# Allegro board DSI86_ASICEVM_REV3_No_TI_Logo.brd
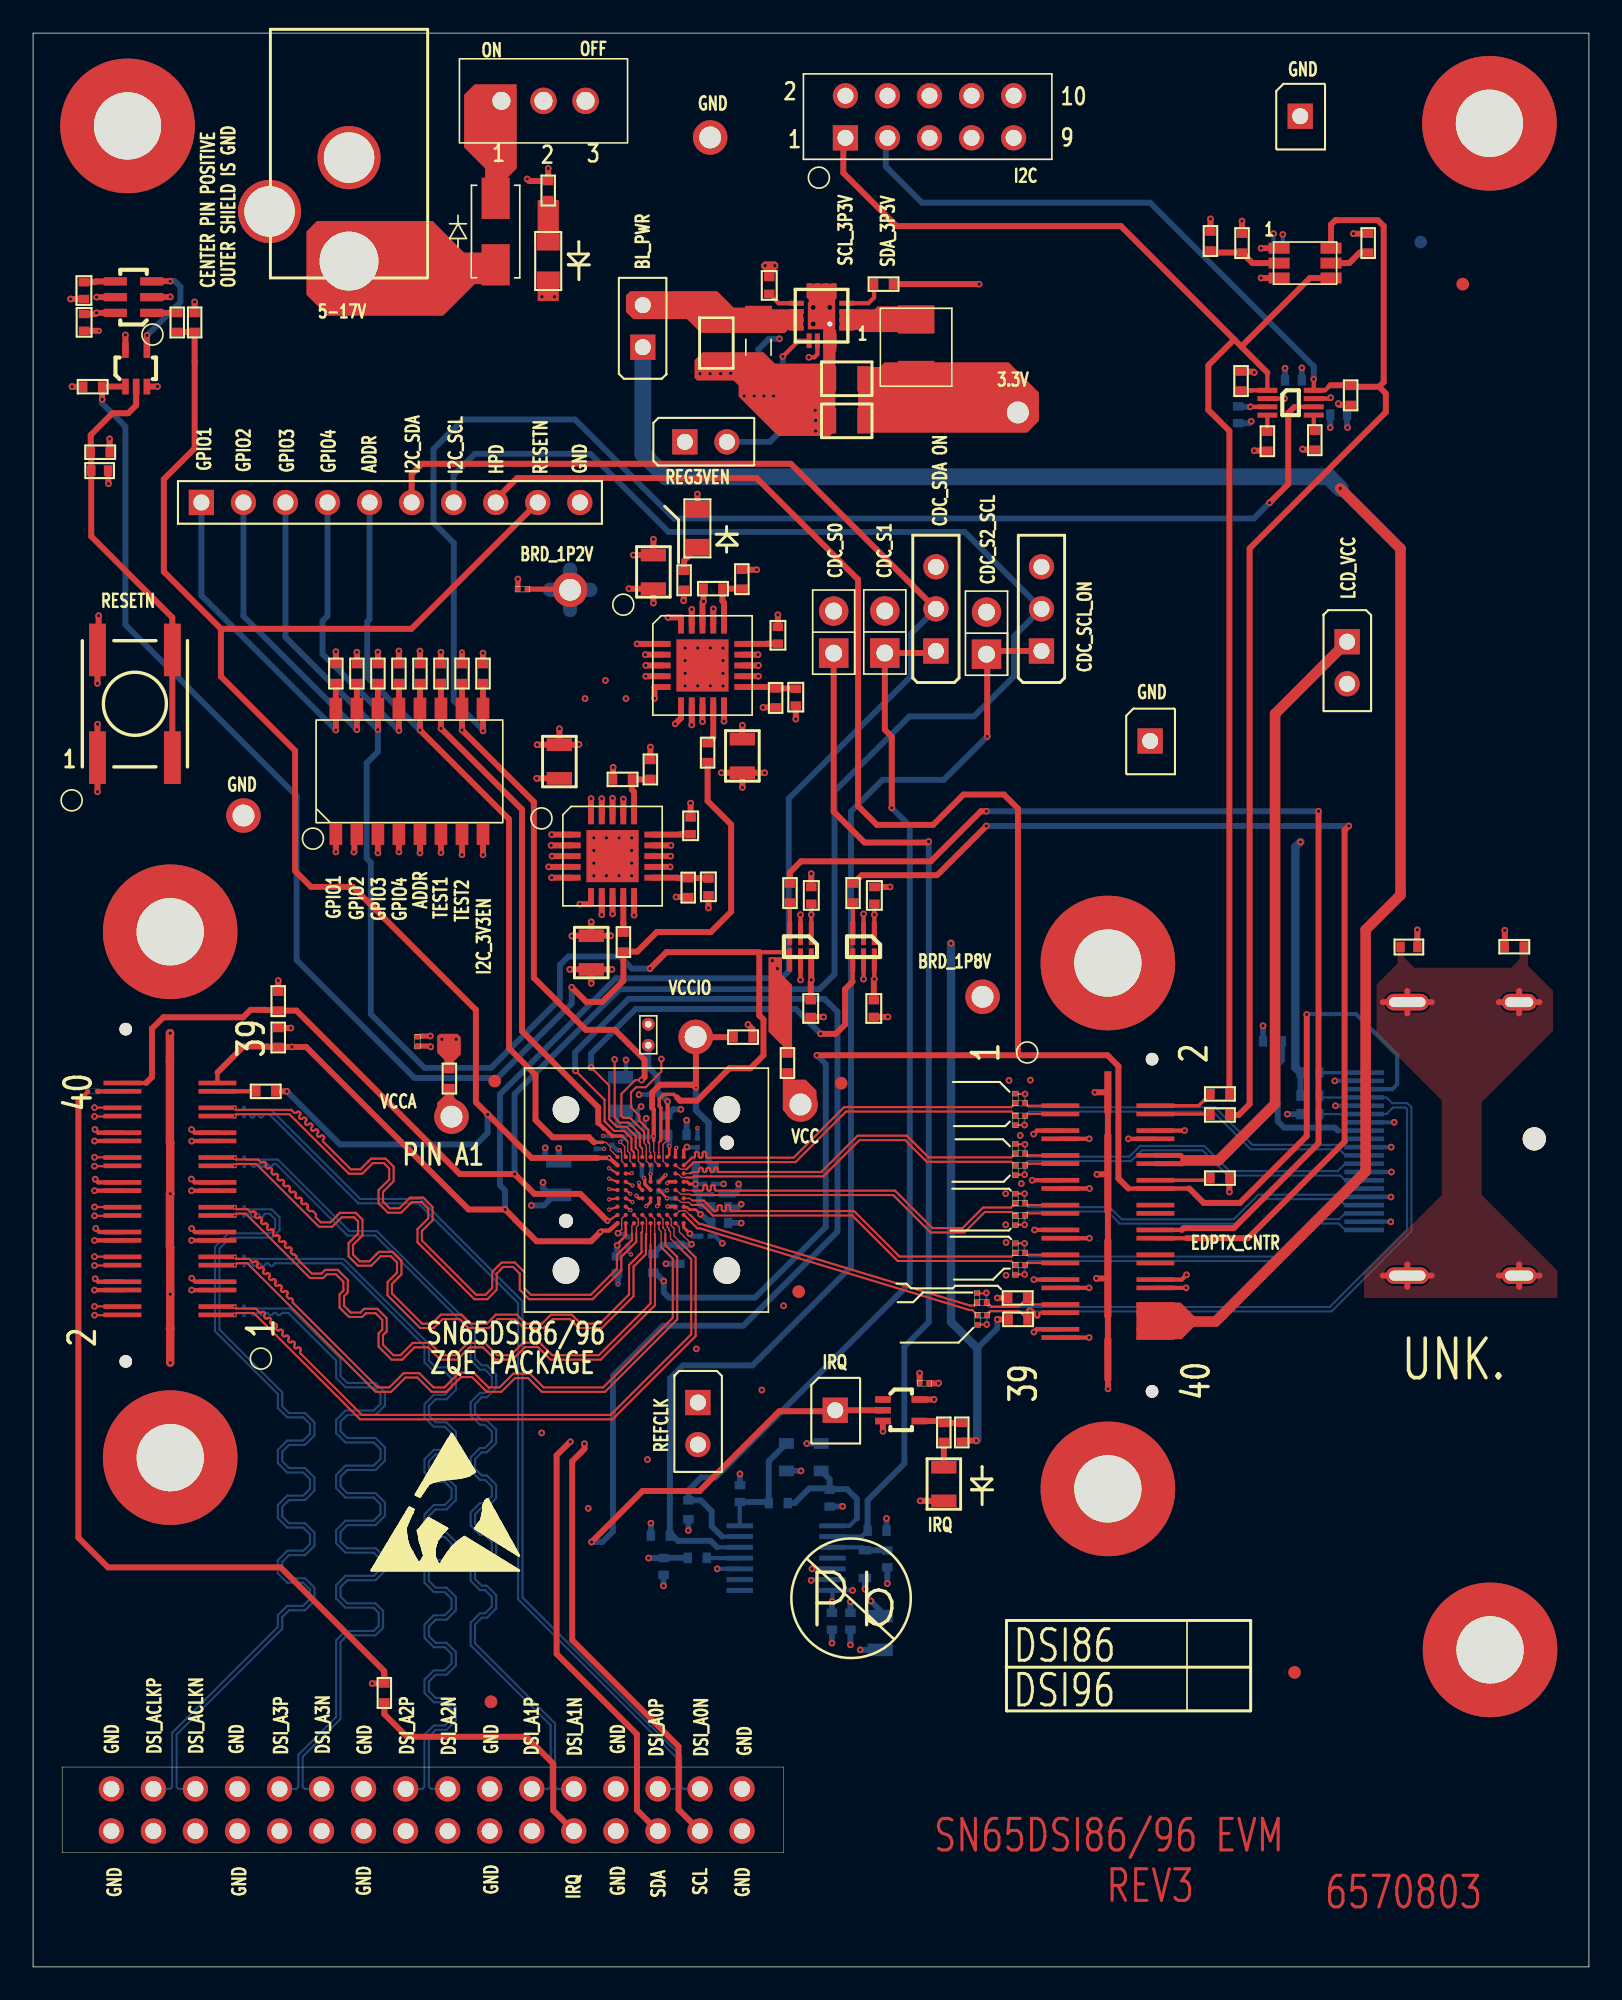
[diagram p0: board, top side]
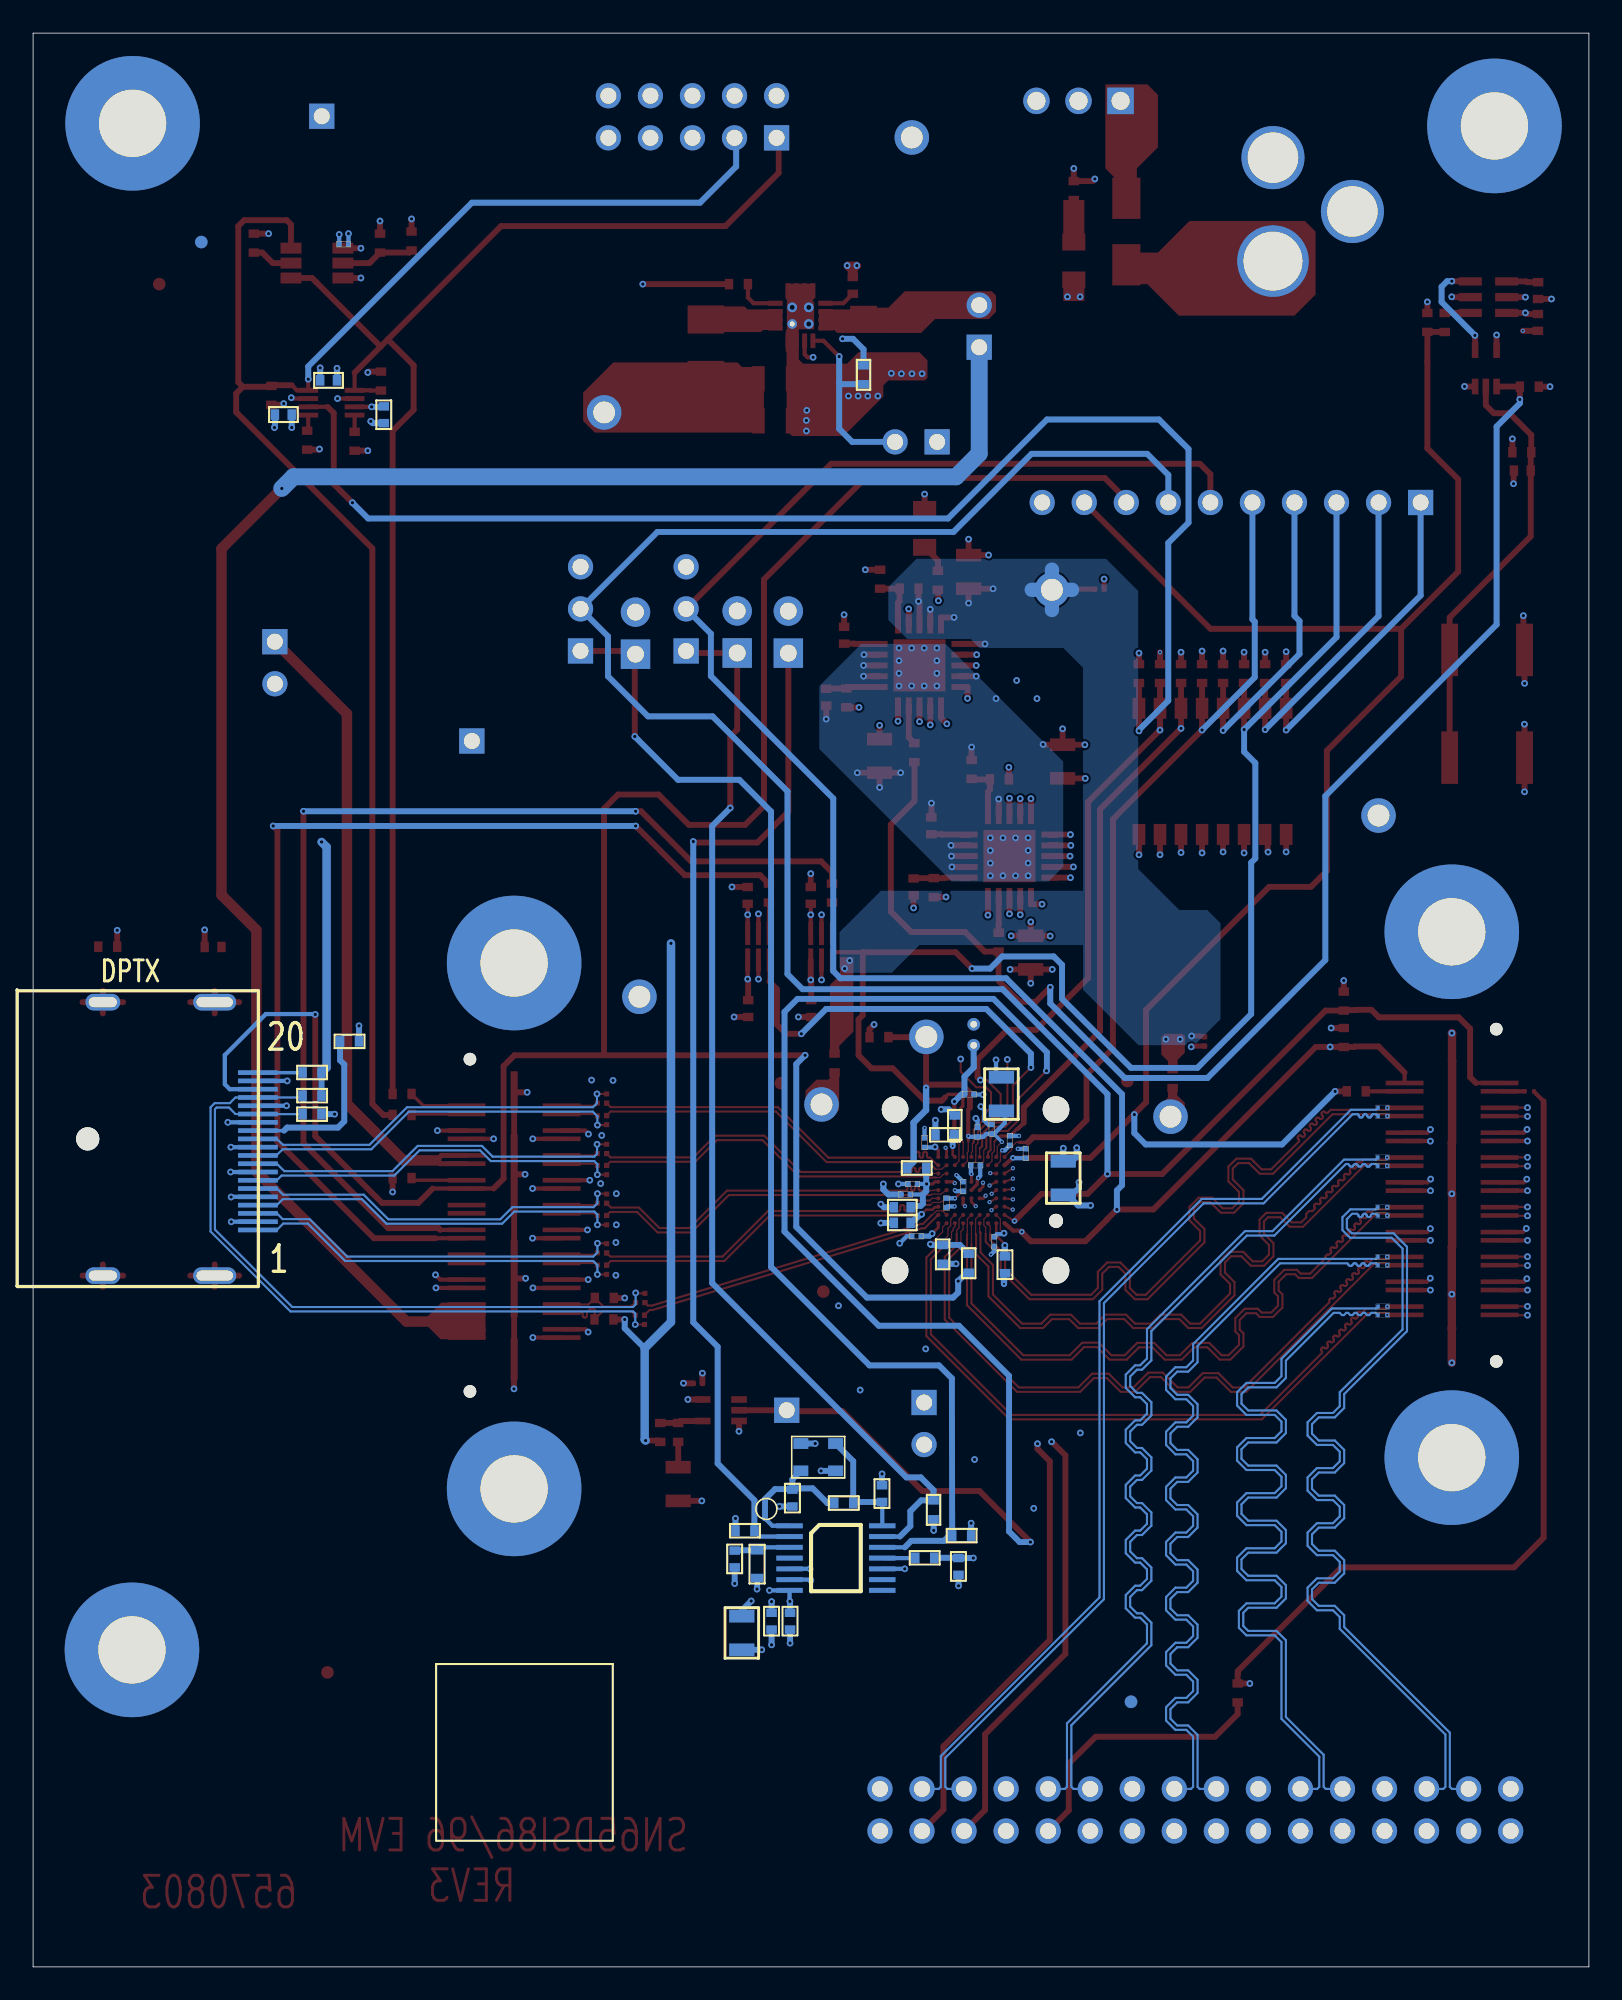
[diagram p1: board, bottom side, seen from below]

Outline 93.98 x 116.75 mm; copper layers: TOP, L2_GND, L3_SIG, L4_PWR, L5_GND, BOTTOM. Coordinates in mm from the lower left corner of the outline.
Outline path: 0,116.75 0,0 93.98,0 93.98,116.75 0,116.75

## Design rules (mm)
constraint set DEFAULT: min track width 0.356
net group AUX: nets AUXN AUXP
net group DIFFPAIR5: nets DSI_A0N DSI_A0P
net group DIFFPAIR6: nets DSI_A1N DSI_A1P
net group DIFFPAIR7: nets DSI_A2N DSI_A2P
net group DIFFPAIR8: nets DSI_A3N DSI_A3P
net group DIFFPAIR9: nets DSI_ACLKN DSI_ACLKP
net group DIFFPAIR10: nets DSI_B0N DSI_B0P
net group DIFFPAIR11: nets DSI_B1N DSI_B1P
net group DIFFPAIR12: nets DSI_B2N DSI_B2P
net group DIFFPAIR13: nets DSI_B3N DSI_B3P
net group DIFFPAIR14: nets DSI_BCLKN DSI_BCLKP
net group DIFFPAIR35: nets FX_CLKN FX_CLKP
net group DIFFPAIR36: nets FX_N0 FX_P0
net group DIFFPAIR37: nets FX_N1 FX_P1
net group DIFFPAIR38: nets FX_N2 FX_P2
net group DIFFPAIR39: nets FX_N3 FX_P3
net group DP_AUX: nets DP_AUXN DP_AUXP
net group EDP_AUX: nets EDP_AUXN EDP_AUXP
net group EDP_ML0: nets EDP_ML0N EDP_ML0P
net group EDP_ML1: nets EDP_ML1N EDP_ML1P
net group EDP_ML2: nets EDP_ML2N EDP_ML2P
net group EDP_ML3: nets EDP_ML3N EDP_ML3P
net group DP_M: nets DP_ML0N DP_ML0P DP_ML1N DP_ML1P DP_ML2N DP_ML2P DP_ML3N DP_ML3P
net group H_DDSS: nets I2C_SCL
net group ML: nets ML0N ML0P ML1N ML1P ML2N ML2P ML3N ML3P

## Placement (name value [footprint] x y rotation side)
C1  10uF  [CC0805]  35.49 51.68 90 bottom
C2  1.0uF  [CC0402]  35.26 42.95 270 bottom
C3  0.1uF  [CC0201]  37.33 48.4 180 bottom
C4  0.1uF  [CC0201]  36.07 50.29 90 bottom
C5  0.01uF  [CC0201]  37.8 47.4 270 bottom
C6  0.1uF  [CC0201]  36.93 50.11 90 bottom
C7  0.1uF  [CC0201]  40.34 44.12 0 bottom
C8  0.01uF  [CC0201]  40.56 47.27 0 bottom
C9  0.1uF  [CC0201]  53.55 35.23 0 top
C10  DNI  [CC0201]  34.01 48.83 90 bottom
C11  1.0uF  [CC0402]  40.92 44.91 0 bottom
C22  220pF  [CC0402]  3.09 101.77 270 top
C23  0.1uF  [CC0402]  3.1 99.85 270 top
C24  18pF  [CC0402]  3.46 90.36 0 top
C25  DNI  [CC0402]  48.13 27.75 90 bottom
C26  DNI  [CC0402]  42.69 29.13 270 bottom
C27  22uF  [CC0805]  51.17 21.18 270 bottom
C28  1.0uF  [CC0402]  78.31 93.71 0 bottom
C29  0.1uF  [CC0402]  76.69 95.81 180 bottom
C30  0.1uF  [CC0402]  72.78 94.27 270 bottom
C31  0.1uF  [CC0402]  51.58 25.19 270 bottom
C32  0.1uF  [CC0402]  49.36 21.43 270 bottom
C33  0.1uF  [CC0402]  48.24 21.43 270 bottom
C35  10uF  [CC0805]  41.27 99.06 270 top
C36  22uF  [CC1206]  43.81 97.79 270 top
C37  22uF  [CC0805]  50.16 93.34 180 top
C38  10uF  [CC0805]  50.16 95.89 180 top
C39  10uF  [CC0805]  42.84 74.13 270 top
C40  3.3nF  [CC0402]  44.45 100.97 90 top
C42  10uF  [CC0805]  37.47 83.21 90 top
C43  0.01uF  [CC0402]  46.09 77.22 270 top
C44  DNI  [CC0402]  44.98 79.84 90 top
C45  10uF  [CC0805]  33.72 62.26 270 top
C46  10uF  [CC0805]  31.79 71.76 90 top
C47  0.01uF  [CC0402]  40.81 65.77 270 top
C48  DNI  [CC0402]  39.7 68.34 90 top
C55  DNI  [CC0402]  38.07 24.74 270 bottom
C56  0.1uF  [CC0201]  38.81 46.41 270 bottom
C57  10uF  [CC0805]  31.75 48.64 270 bottom
C58  0.01uF  [CC0201]  34.97 49.61 90 bottom
C59  0.1uF  [CC0201]  35.93 44.07 270 bottom
C60  0.01uF  [CC0201]  40.13 49.48 90 bottom
C61  0.1uF  [CC0201]  23.21 56.15 270 top
C62  0.1uF  [CC0201]  29.84 83.19 180 top
C63  DNI  [CC0201]  59.33 52.15 0 top
C64  DNI  [CC0201]  59.33 51.38 0 top
C65  DNI  [CC0201]  59.34 49.1 0 top
C66  DNI  [CC0201]  59.34 48.39 0 top
C67  DNI  [CC0201]  59.34 46.11 0 top
C68  DNI  [CC0201]  59.34 45.37 0 top
C69  DNI  [CC0201]  59.34 43.11 0 top
C70  DNI  [CC0201]  59.34 42.37 0 top
C71  DNI  [CC0201]  57.02 40.11 0 top
C72  DNI  [CC0201]  57.05 39.35 0 top
C73  0.1uF  [CC0201]  59.33 52.15 90 top
C74  0.1uF  [CC0201]  59.33 51.41 270 top
C75  0.1uF  [CC0201]  59.33 49.11 90 top
C76  0.1uF  [CC0201]  59.33 48.39 270 top
C77  0.1uF  [CC0201]  59.33 46.1 90 top
C78  0.1uF  [CC0201]  59.33 45.36 270 top
C79  0.1uF  [CC0201]  59.33 43.1 90 top
C80  0.1uF  [CC0201]  59.33 42.37 270 top
C81  0.1uF  [CC0201]  57.02 40.11 90 top
C82  0.1uF  [CC0201]  57.05 39.34 270 top
C83  1.0uF  [CC0402]  82.55 61.59 0 top
C84  DNI  [CC0201]  37.72 52.68 180 bottom
C85  0.1uF  [CC0402]  46.99 64.14 90 top
C86  0.1uF  [CC0402]  46.99 58.42 270 top
C87  0.1uF  [CC0402]  50.8 64.14 90 top
C88  0.1uF  [CC0402]  50.8 58.42 270 top
C89  0.1uF  [CC0201]  74.93 104.01 0 bottom
C90  0.1uF  [CC0201]  41 46.63 0 bottom
C91  1.0uF  [CC0402]  40.92 45.85 0 bottom
D1  LED Orange 0805  [CC0805]  55.01 30.17 270 top
D3  LED Green 0805  [R0805]  31.11 104.14 270 top
D6  LED RED 0805  [R0805]  40.13 85.71 90 top
D8  20V, 1A  [DO214AC]  27.94 104.78 270 top
FB4  220 @ 100MHZ  [R0603]  50.25 25.15 270 bottom
J1  2x16 Header Male  [BERG2X16]  42.82 10.74 270 top
J4  QSH-020-01  [QSH-020_X]  8.26 56.62 90 top
J6  QSH-020-01  [QSH-020_X]  64.92 34.75 270 top
J7  HDR2X1 M .1  [HDR_2X1]  48.36 79.32 0 top
J8  HDR2X1 M .1  [HDR_2X1]  51.45 79.33 0 top
J9  Display_Port_Connector_Source  [DISPLAYPORT]  90.68 49.99 270 bottom
J10  Header 5x2 0.1" thru-hole  [BERG2X5]  49.07 110.43 90 top
J11  HDR2X1 M .1  [HDR_2X1]  57.59 79.26 0 top
J13  2.1mm x 5.5mm  [PJ-202AH]  19.08 102.99 180 top
J14  HDR2X1 M .1  [BERG1X2]  39.37 92.08 90 top
J16  HEADER 1x10  [BERG1X10]  20.31 88.42 90 top
J17  HDR2X1 M .1  [BERG1X2]  40.16 34.07 0 top
J18  HDR3X1 M .1  [BERG1X3]  54.53 79.45 180 top
J19  HDR3X1 M .1  [BERG1X3]  60.91 79.45 180 top
J20  HDR2X1 M .1  [BERG1X2]  36.83 97.79 180 top
J21  HDR2X1 M .1  [BERG1X2]  79.38 80.01 0 top
L1  2.2uH  [4P5X4MM]  53.34 97.79 270 top
LP1  LP  [TESTLOOP]  57.35 58.57 0 top
LP2  LP  [TESTLOOP]  40.02 56.15 0 top
LP3  LP  [TESTLOOP]  46.35 52.07 0 top
LP4  LP  [TESTLOOP]  12.71 69.51 0 top
LP5  LP  [TESTLOOP]  40.9 110.45 0 top
LP6  LP  [TESTLOOP]  59.49 93.85 0 top
LP7  LP  [TESTLOOP]  32.44 83.14 0 top
LP9  LP  [TESTLOOP]  25.27 51.33 0 top
NOREF  -  [unnamed]  48.81 53.35 0 top
NOREF#2  -  [#2]  90.62 41.71 0 top
NOREF#3  -  [unnamed#3]  8.28 30.75 0 top
NOREF#4  -  [unnamed#3]  8.28 62.5 0 top
NOREF#5  -  [unnamed]  27.88 53.48 0 top
NOREF#6  -  [#2]  0 116.75 0 top
NOREF#7  -  [unnamed#3]  64.92 28.86 0 top
NOREF#8  -  [#2]  0 0 0 top
NOREF#9  -  [unnamed]  46.25 40.77 0 top
NOREF#10  -  [#2]  -12.7 -12.7 0 top
NOREF#11  -  [#2]  81.91 41.7 0 top
NOREF#12  -  [#2]  90.34 58.55 0 top
NOREF#13  -  [#2]  25.12 27.46 0 top
NOREF#14  -  [#2]  93.98 0 0 top
NOREF#15  -  [#2]  49.41 22.26 0 top
NOREF#16  -  [unnamed#3]  88.01 19.14 0 top
NOREF#17  -  [#2]  101.6 127 0 top
NOREF#18  -  [unnamed#3]  64.92 60.61 0 top
NOREF#19  -  [#2]  84.11 41.71 0 top
NOREF#20  -  [#2]  -12.7 127 0 top
NOREF#21  -  [unnamed]  86.36 101.6 0 top
NOREF#22  -  [unnamed#3]  5.7 111.15 0 top
NOREF#23  -  [#2]  0 0 0 top
NOREF#24  -  [unnamed#3]  87.97 111.31 0 top
NOREF#25  -  [#2]  90.35 57.95 0 top
NOREF#26  -  [#2]  88.92 41.71 0 top
NOREF#27  -  [unnamed]  27.66 16 0 top
NOREF#28  -  [unnamed]  76.2 17.78 0 top
NOREF#29  -  [#2]  90.36 42.04 0 top
NOREF#30  -  [#2]  90.36 41.44 0 top
NOREF#31  -  [#2]  64.35 13 180 bottom
NOREF#32  -  [unnamed]  27.66 16 180 bottom
NOREF#33  -  [unnamed]  83.82 104.14 180 bottom
R1  1K  [R0402]  56.1 31.7 90 top
R2  350  [R0402]  55.01 31.7 90 top
R3  4.7K  [R0402]  14.81 58.88 270 top
R4  4.7K  [R0402]  14.81 56.69 270 top
R5  10nF  [R0402]  39.04 43.59 270 bottom
R6  0  [R0201]  12.18 45.36 0 bottom
R7  0  [R0201]  12.19 45.86 0 bottom
R8  0  [R0201]  12.18 51.37 0 bottom
R9  0  [R0201]  12.18 51.87 0 bottom
R10  0  [R0201]  12.19 48.36 0 bottom
R11  0  [R0201]  12.19 48.87 0 bottom
R12  0  [R0201]  12.18 42.37 0 bottom
R13  0  [R0201]  12.19 42.87 0 bottom
R14  0  [R0201]  12.18 39.36 0 bottom
R15  0  [R0201]  12.17 39.86 0 bottom
R16  DNI  [R0402]  21.22 15.97 90 top
R27  100K  [R0402]  76.56 52.6 0 bottom
R29  0  [R0402]  13.48 52.86 0 top
R33  1M  [R0402]  88.9 61.59 0 top
R36  1M  [R0402]  74.3 55.88 0 bottom
R51  DNI  [R0402]  9.76 99.86 270 top
R52  0  [R0402]  8.71 98.71 90 top
R53  1K  [R0402]  4.62 91.45 180 top
R54  4.7K  [R0402]  18.29 77.52 90 top
R55  4.7K  [R0402]  19.56 77.52 90 top
R56  4.7K  [R0402]  20.83 77.52 90 top
R57  4.7K  [R0402]  22.1 77.52 90 top
R58  4.7K  [R0402]  23.37 77.52 90 top
R59  4.7K  [R0402]  24.64 77.52 90 top
R60  4.7K  [R0402]  25.91 77.52 90 top
R61  4.7K  [R0402]  27.18 77.52 90 top
R66  DNI  [R0402]  45.58 28 180 bottom
R67  18  [R0402]  39.55 24.7 0 bottom
R70  0  [R0201]  3.87 52.87 180 top
R72  10K  [R0402]  37.32 26.04 0 bottom
R73  10K  [R0402]  39.59 27.03 90 bottom
R74  10K  [R0402]  51.55 26.33 180 bottom
R75  0  [R0402]  77.42 91.61 90 top
R76  0  [R0402]  74.56 91.54 90 top
R77  4.7K  [R0402]  72.97 96.32 270 top
R78  4.7K  [R0402]  79.59 94.31 90 top
R79  4.7K  [R0402]  44.85 76.04 90 top
R80  0  [R0402]  40.74 72.74 90 top
R81  500  [R0402]  31.11 106.68 90 top
R82  2.49K  [R0402]  41.64 83.21 180 top
R83  100K  [R0402]  50.8 101.6 0 top
R84  4.99K  [R0402]  42.81 84.36 270 top
R86  10K  [R0402]  43.81 96.7 270 bottom
R87  4.7K  [R0402]  39.57 64.59 90 top
R88  0  [R0402]  35.66 61.3 90 top
R89  3.57K  [R0402]  36.18 71.7 180 top
R90  2.87K  [R0402]  37.29 72.87 270 top
R101  350  [R0402]  39.32 84.29 270 top
R103  10K  [R0402]  4.17 95.41 180 top
R104  0  [R0402]  39.47 50.23 180 bottom
R105  DNI  [R0402]  38.3 51.41 270 bottom
R108  0  [R0402]  42.32 56.13 0 top
R109  0  [R0402]  45.57 54 90 top
R110  0  [R0402]  25.15 53.06 90 top
R111  0  [R0402]  37.47 41.91 90 bottom
R112  DNI  [R0402]  77.7 54 180 bottom
R113  100K  [R0402]  77.7 51.49 180 bottom
R114  100K  [R0402]  58.93 39.09 0 top
R115  100K  [R0402]  60.05 40.39 180 top
R116  DNI  [R0402]  71.12 51.44 0 top
R117  DNI  [R0402]  71.12 52.7 0 top
R118  0  [R0402]  41.17 48.23 180 bottom
R186  0  [R0402]  45.72 65.41 270 top
R187  0  [R0402]  49.53 65.41 270 top
R188  4.7K  [R0402]  71.12 104.78 270 top
R189  DNI  [R0402]  73.03 103.5 90 top
R191  4.7K  [R0402]  80.64 103.5 90 top
R192  4K  [R0402]  71.12 47.62 0 top
SW1  PB_SWITCH  [SW_MOM_2NO]  6.15 76.26 0 top
SW2  8-POS 50-MIL SMT  [TDA08H0SK1]  22.73 72.18 0 top
SW6  -  [TS01CQE]  28.29 112.67 270 top
TP1  T POINT S  [BERG1X1]  48.46 33.61 0 top
TP5  T POINT S  [BERG1X1]  67.48 74.01 0 top
TP6  T POINT S  [BERG1X1]  76.54 111.74 0 top
U1  SN65DSI86  [IRONWOOD_81PIN_7048]  32.19 51.76 180 top
U2  SN74LVC1G07DCK  [DCK5]  52.44 33.61 0 top
U3  TPS3808  [DBV_R-PDSO-G6]  6.07 100.81 180 top
U4  SN74LVC1G08DCK  [DCK5]  6.23 96.52 90 top
U5  CDCEL913PW  [PW14]  45.49 24.68 180 bottom
U6  txs0102dcut  [DCU8]  75.96 94.44 0 top
U8  TPS74201RGWT  [RGW20]  40.44 78.58 0 top
U9  TPS74201RGWT  [RGW20]  35 67.06 0 top
U11  SN74AVC1T45DCKR  [DCK6]  46.35 61.59 270 top
U12  SN74AVC1T45DCKR  [DCK6]  50.16 61.59 270 top
U13  TSL2561T  [TMB6]  76.83 102.87 0 top
U14  TPS62142RGTR  [RGT16]  47.62 99.69 180 top
UNK.  -  [#2]  79.65 29.11 0 top
XC17  XC  [JMP_2P]  37.16 55.64 90 top
Y1  27MHZ _crystal  [ABM8]  46.55 30.77 270 bottom

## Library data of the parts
C1-C11 C22-C33 C43 C44 C47 C48 C55-C91 = CAP NP
C35-C39 C42 C45 C46 = CAP_0
C40 = cc0402
D1 D3 D6 = DIODE
D8 = BAT60A
FB4 = FERRITE BEAD
J1 = 2x16 Header Male
J4 J6 = QSH-020-01_3
J7 J8 J11 J14 J17 J20 J21 = HDR2X1 M .1
J9 = Display_Port_Connector_Source_0
J10 = CONN PCB 5x2-S
J13 = BNC_2
J16 = HEADER 10
J18 J19 = HDR3X1 M .1
L1 = INDUCTOR FERRITE
LP1-LP7 LP9 = TESTLOOP
NOREF NOREF#5 NOREF#9 = -: User Part Number: D*
R1-R16 R27 R29 R51-R61 R66 R67 R70 R72-R84 R86-R90 R101 R103-R105 R108-R118 R188 R189 R191 R192 = R_4
R33 R36 R186 R187 = R
SW1 = PB_SWITCH_0
SW2 = SW DIP-8/SM_0
SW6 = SW_SLIDE_SPDT2
TP1 TP5 TP6 = T POINT S
U1 = SN65DSI86
U2 = SN74LVC1G07_0
U3 = TPS3808
U4 = SN74AHC1G08DCK_2
U5 = CDCEL913PW
U6 = txs0102dcut_2
U8 U9 = TPS74401RGWT_0
U11 U12 = SN74AVC1T45DCKR
U13 = TSL2561T
U14 = TPS62142RGTR
XC17 = XCON_0
Y1 = 27MHZ _crystal

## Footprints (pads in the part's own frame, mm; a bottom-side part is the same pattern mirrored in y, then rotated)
4P5X4MM
  rect 1.702x2.21 smd: 1(-1.676,0) 2(1.676,0)
ABM8
  rect 0.65x0.9 smd: 1(-0.825,1.05) 2(-0.825,-1.05) 3(0.825,-1.05) 4(0.825,1.05)
BERG1X1
  rect 1.524x1.524 hole 0.965: 1(0,0)
BERG1X2
  rect 1.524x1.524 hole 0.965: 1(0,0)
  round 1.524 hole 0.965: 2(0,-2.54)
BERG1X3
  rect 1.524x1.524 hole 0.965: 1(0,0)
  round 1.524 hole 0.965: 2(0,-2.54) 3(0,-5.08)
BERG1X10
  rect 1.524x1.524 hole 0.965: 1(0,10.148)
  round 1.524 hole 0.965: 2(0,7.608) 3(0,5.068) 4(0,2.528) 5(0,-0.012) 6(0,-2.552) 7(0,-5.092) 8(0,-7.632) 9(0,-10.172) 10(0,-12.712)
BERG2X5
  rect 1.524x1.524 hole 0.965: 1(0,0)
  round 1.524 hole 0.965: 2(2.54,0) 3(0,-2.54) 4(2.54,-2.54) 5(0,-5.08) 6(2.54,-5.08) 7(0,-7.62) 8(2.54,-7.62) 9(0,-10.16) 10(2.54,-10.16)
BERG2X16
  round 1.524 hole 0.965: 1(0,0) 2(2.54,0) 3(0,-2.54) 4(2.54,-2.54) 5(0,-5.08) 6(2.54,-5.08) 7(0,-7.62) 8(2.54,-7.62) 9(0,-10.16) 10(2.54,-10.16) 11(0,-12.7) 12(2.54,-12.7) 13(0,-15.24) 14(2.54,-15.24) 15(0,-17.78) 16(2.54,-17.78) 17(0,-20.32) 18(2.54,-20.32) 19(0,-22.86) 20(2.54,-22.86) 21(0,-25.4) 22(2.54,-25.4) 23(0,-27.94) 24(2.54,-27.94) 25(0,-30.48) 26(2.54,-30.48) 27(0,-33.02) 28(2.54,-33.02) 29(0,-35.56) 30(2.54,-35.56) 31(0,-38.1) 32(2.54,-38.1)
CC0201
  rect 0.305x0.305 smd: 1(0,0) 2(0.559,0)
CC0402
  rect 0.508x0.635 smd: 1(0.051,-0.015) 2(1.067,-0.015)
CC0805
  rect 0.762x1.524 smd: 1(0,0) 2(2.032,0)
CC1206
  rect 1.575x1.626 smd: 1(-1.714,0) 2(1.714,0)
DBV_R-PDSO-G6
  rect 1.4x0.5 smd: 1(-1.1,0.95) 2(-1.1,0) 3(-1.1,-0.95) 4(1.1,-0.95) 5(1.1,0) 6(1.1,0.95)
DCK5
  rect 0.95x0.4 smd: 1(-1.1,0.65) 2(-1.1,0) 3(-1.1,-0.65) 4(1.1,-0.65) 5(1.1,0.65)
DCK6
  rect 1.4x0.3 smd: 1(-0.8,0.65) 2(-0.8,0) 3(-0.8,-0.65) 4(0.8,-0.65) 5(0.8,0) 6(0.8,0.65)
DCU8
  rect 1.2x0.3 smd: 1(-1.4,0.75) 2(-1.4,0.25) 3(-1.4,-0.25) 4(-1.4,-0.75) 5(1.4,-0.75) 6(1.4,-0.25) 7(1.4,0.25) 8(1.4,0.75)
DISPLAYPORT
  round 1.4 hole 1.4 unplated: (0,0)
  rect 0.28x2.4 smd: 1(5.5,10.28) 2(5,10.28) 3(4.5,10.28) 4(4,10.28) 5(3.5,10.28) 6(3,10.28) 7(2.5,10.28) 8(2,10.28) 9(1.5,10.28) 10(1,10.28) 11(0.5,10.28) 12(0,10.28) 13(-0.5,10.28) 14(-1,10.28) 15(-1.5,10.28) 16(-2,10.28) 17(-2.5,10.28) 18(-3,10.28) 19(-3.5,10.28) 20(-4,10.28)
  oval 1x2.6 hole 0.6x2.2: 21(-8.255,7.671) 22(8.255,7.671)
  oval 1x2.1 hole 0.6x1.7: 23(-8.255,0.914) 24(8.255,0.914)
DO214AC
  rect 2.489x1.702 smd: 1(-2.007,0) 2(2.007,0)
HDR_2X1
  rect 1.778x1.778 hole 1.016: 1(0,0)
  round 1.778 hole 1.016: 2(0,2.54)
IRONWOOD_81PIN_7048
  round 1.61 hole 1.61 unplated: (-9.72,9.72) (-9.72,0) (0,9.72) (0,0)
  round 0.85 hole 0.85 unplated: (-9.72,2) (0,6.72)
  round 0.254 smd: A1(-3.11,2.86) A2(-3.61,2.86) A3(-4.11,2.86) A4(-4.61,2.86) A5(-5.11,2.86) A6(-5.61,2.86) A7(-6.11,2.86) A8(-6.61,2.86) A9(-7.11,2.86) B1(-3.11,3.36) B2(-3.61,3.36) B3(-4.11,3.36) B4(-4.61,3.36) B5(-5.11,3.36) B6(-5.61,3.36) B7(-6.11,3.36) B8(-6.61,3.36) B9(-7.11,3.36) C1(-3.11,3.86) C2(-3.61,3.86) C8(-6.61,3.86) C9(-7.11,3.86) D1(-3.11,4.36) D2(-3.61,4.36) D5(-5.11,4.36) D6(-5.61,4.36) D8(-6.61,4.36) D9(-7.11,4.36) E1(-3.11,4.86) E2(-3.61,4.86) E4(-4.61,4.86) E5(-5.11,4.86) E6(-5.61,4.86) E8(-6.61,4.86) E9(-7.11,4.86) F1(-3.11,5.36) F2(-3.61,5.36) F4(-4.61,5.36) F5(-5.11,5.36) F6(-5.61,5.36) F8(-6.61,5.36) F9(-7.11,5.36) G1(-3.11,5.86) G2(-3.61,5.86) G8(-6.61,5.86) G9(-7.11,5.86) H1(-3.11,6.36) H2(-3.61,6.36) H3(-4.11,6.36) H4(-4.61,6.36) H5(-5.11,6.36) H6(-5.61,6.36) H7(-6.11,6.36) H8(-6.61,6.36) H9(-7.11,6.36) J1(-3.11,6.86) J2(-3.61,6.86) J3(-4.11,6.86) J4(-4.61,6.86) J5(-5.11,6.86) J6(-5.61,6.86) J7(-6.11,6.86) J8(-6.61,6.86) J9(-7.11,6.86)
JMP_2P
  round 0.762 hole 0.406: 1(0,0) 2(1.27,0)
PJ-202AH
  round 4.318 hole 3.556: 1(0,0)
  round 3.81 hole 3.048: 2(4.801,-2.997) 3(0,-6.248)
PW14
  rect 1.6x0.3 smd: 1(-2.8,1.95) 2(-2.8,1.3) 3(-2.8,0.65) 4(-2.8,0) 5(-2.8,-0.65) 6(-2.8,-1.3) 7(-2.8,-1.95) 8(2.8,-1.95) 9(2.8,-1.3) 10(2.8,-0.65) 11(2.8,0) 12(2.8,0.65) 13(2.8,1.3) 14(2.8,1.95)
QSH-020_X
  round 0.762 hole 1.016 unplated: (-20.06,2.67) (0,2.67)
  rect 0.279x2.286 smd: 1(-17.25,-2.87) 2(-17.25,2.87) 3(-16.75,-2.87) 4(-16.75,2.87) 5(-15.75,-2.87) 6(-15.75,2.87) 7(-15.25,-2.87) 8(-15.25,2.87) 9(-14.25,-2.87) 10(-14.25,2.87) 11(-13.75,-2.87) 12(-13.75,2.87) 13(-12.75,-2.87) 14(-12.75,2.87) 15(-12.25,-2.87) 16(-12.25,2.87) 17(-11.25,-2.87) 18(-11.25,2.87) 19(-10.75,-2.87) 20(-10.75,2.87) 21(-9.75,-2.87) 22(-9.75,2.87) 23(-9.25,-2.87) 24(-9.25,2.87) 25(-8.25,-2.87) 26(-8.25,2.87) 27(-7.75,-2.87) 28(-7.75,2.87) 29(-6.75,-2.87) 30(-6.75,2.87) 31(-6.25,-2.87) 32(-6.25,2.87) 33(-5.25,-2.87) 34(-5.25,2.87) 35(-4.75,-2.87) 36(-4.75,2.87) 37(-3.75,-2.87) 38(-3.75,2.87) 39(-3.25,-2.87) 40(-3.25,2.87)
  rect 2.54x0.432 smd: G1(-18.06,0) G4(-1.93,0)
  rect 4.699x0.432 smd: G2(-13.17,0) G3(-6.82,0)
R0201
  rect 0.203x0.254 smd: 1(0,0) 2(0.559,0)
R0402
  rect 0.508x0.635 smd: 1(0,0) 2(1.143,0)
R0603
  rect 0.508x0.762 smd: 1(0,0) 2(1.676,0)
R0805
  rect 1.016x1.397 smd: 1(0,0) 2(2.286,0)
RGT16
  rect 0.889x0.305 smd: 1(-1.516,0.75) 2(-1.516,0.25) 3(-1.516,-0.25) 4(-1.516,-0.75) 9(1.516,-0.75) 10(1.516,-0.25) 11(1.516,0.25) 12(1.516,0.75)
  rect 0.305x0.889 smd: 5(-0.75,-1.516) 6(-0.25,-1.516) 7(0.25,-1.516) 8(0.75,-1.516) 13(0.75,1.516) 14(0.25,1.516) 15(-0.25,1.516) 16(-0.75,1.516)
  round 0.584 hole 0.305: 17(-0.5,0.5)
RGW20
  rect 1.016x0.356 smd: 1(-2.433,1.301) 2(-2.433,0.65) 3(-2.433,0) 4(-2.433,-0.65) 5(-2.433,-1.301) 11(2.433,-1.301) 12(2.433,-0.65) 13(2.433,0) 14(2.433,0.65) 15(2.433,1.301)
  rect 0.356x1.016 smd: 6(-1.301,-2.433) 7(-0.65,-2.433) 8(0,-2.433) 9(0.65,-2.433) 10(1.301,-2.433) 16(1.301,2.433) 17(0.65,2.433) 18(0,2.433) 19(-0.65,2.433) 20(-1.301,2.433)
  rect 3.15x3.15 smd: 21(0,0)
SW_MOM_2NO
  rect 1.016x3.175 smd: 1(-2.261,-3.251) 2(-2.261,3.251) 3(2.261,-3.251) 4(2.261,3.251)
TDA08H0SK1
  rect 0.762x1.27 smd: 1(-4.445,-3.81) 2(-3.175,-3.81) 3(-1.905,-3.81) 4(-0.635,-3.81) 5(0.635,-3.81) 6(1.905,-3.81) 7(3.175,-3.81) 8(4.445,-3.81) 9(4.445,3.81) 10(3.175,3.81) 11(1.905,3.81) 12(0.635,3.81) 13(-0.635,3.81) 14(-1.905,3.81) 15(-3.175,3.81) 16(-4.445,3.81)
TESTLOOP
  round 2.083 hole 1.321: 1(0,0)
TMB6
  rect 1.27x0.66 smd: 1(-1.568,0.899) 2(-1.568,0) 3(-1.568,-0.899) 4(1.568,-0.899) 5(1.568,0) 6(1.568,0.899)
TS01CQE
  rect 1.6x1.6 hole 1.092: 1(0,0)
  round 1.6 hole 1.092: 2(0,2.54) 3(0,5.08)
unnamed
  round 0.762 smd: 1(0,0)
unnamed#3
  round 8.128 hole 4.064: (0,0)

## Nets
9V_DIODE: D8.2 J13.1(T)
GND: C1.2 C2.2 C3.2 C4.2 C5.2 C6.2 C7.2 C8.2 C9.2 C10.2 C11.2 C22.2 C23.2 C24.2 C25.1 C26.1 C27.2 C28.2 C29.2 C30.2 C31.2 C32.2 C33.2 C35.2 C36.2 C37.2 C38.2 C39.2 C40.2 C42.2 C43.2 C44.2 C45.2 C46.2 C47.2 C48.2 C55.2 C56.2 C57.2 C58.2 C59.2 C60.2 C61.2 C62.2 C83.2 C84.2 C85.2 C86.2 C87.2 C88.2 C89.2 C90.2 C91.2 D1.2(K) D3.2(K) D6.2(K) J1.1 J1.2 J1.7 J1.8 J1.13 J1.14 J1.19 J1.20 J1.25 J1.26 J1.31 J1.32 J4.5 J4.6 J4.7 J4.8 J4.13 J4.14 J4.15 J4.16 J4.21 J4.22 J4.23 J4.24 J4.29 J4.30 J4.31 J4.32 J4.G1 J4.G2 J4.G3 J4.G4 J6.5 J6.6 J6.7 J6.8 J6.13 J6.15 J6.21 J6.23 J6.29 J6.30 J6.31 J6.32 J6.37 J6.39 J6.G1 J6.G2 J6.G3 J6.G4 J7.2 J8.2 J9.2 J9.5 J9.8 J9.11 J9.14 J9.16 J9.19(RTN) J10.2 J10.10 J11.2 J13.2 J13.3 J14.1 J16.10 J17.2 J18.3 J19.3 LP4.1 LP5.1 R5.2 R33.1 R36.1 R84.1 R90.1 R113.2 R115.2 R188.1 R192.2 SW1.1 SW1.2 SW2.1 SW2.2 SW2.3 SW2.4 SW2.5 SW2.6 SW2.7 SW2.8 TP5.1(TP) TP6.1(TP) U1.A8 U1.D8 U1.E4 U1.E5 U1.F4 U1.F5 U1.F6 U1.G8 U2.3 U3.2 U4.3 U5.5 U5.10 U6.2 U8.2 U8.3 U8.4 U8.12 U8.13 U8.14 U8.17 U8.21 U9.2 U9.3 U9.4 U9.12 U9.13 U9.14 U9.17 U9.21 U11.2 U11.5 U12.2 U12.5 U13.3 U14.5 U14.6 U14.7 U14.8 U14.15 U14.16 U14.17 Y1.2 Y1.4
VCC: C2.1 C3.1 C5.1 C7.1 LP3.1 R109.1 U1.D5 U1.D6 U1.J2 U1.J9
VCCA: C11.1 C56.1 C57.1 C58.1 C59.1 C60.1 LP9.1 R110.1 U1.A9 U1.B2 U1.E6 U1.G9 U1.H2
VCCIO: C1.1 C4.1 C6.1 LP2.1 R108.1 R118.1 U1.A2 U1.B6
VDDPLL: C8.1 C90.1 C91.1 R118.2 U1.D9(VPLL)
A1_SCL: R76.2 U6.4
A1_SDA: R75.2 U6.5
ADDR: J16.5 R58.1 SW2.12 U1.A1
AMUX: C84.1 U1.B7 XC17.1
AUXN: C72.1 C82.1 U1.H9
AUXP: C71.1 C81.1 U1.H8
BOARD_1P2V: C42.1 C61.1 C62.1 LP7.1 R82.2 R109.2 R110.2 U8.1 U8.18 U8.19 U8.20
BOARD_1P8V: C9.1 C23.1 C27.1 C30.1 C32.1 C33.1 C46.1 C86.1 C88.1 FB4.2 LP1.1 R3.1 R4.1 R51.1 R53.1 R54.2 R55.2 R56.2 R57.2 R58.2 R59.2 R60.2 R72.1 R73.1 R74.1 R89.2 R103.2 R108.2 U2.5 U3.5 U3.6(VDD) U4.5 U5.6 U5.7 U6.3 U9.1 U9.18 U9.19 U9.20 U11.6(VCCB) U12.6(VCCB)
BOARD_3P3V: C28.1 C29.1 C37.1 C38.1 C39.1 C45.1 C85.1 C87.1 C89.1 J21.2 L1.2 LP6.1 R1.1 R27.1 R61.2 R77.1 R78.1 R79.1 R83.2 R87.1 R101.2 R112.2 R114.1 R189.2 R191.2 U6.7(VCCB) U8.5 U8.6 U8.7 U8.8 U8.10 U9.5 U9.6 U9.7 U9.8 U9.10 U11.1 U12.1 U13.1(VDD) U14.14(VOS)
BOARD_9V: C35.1 C36.1 J20.2 R81.2 R86.1 SW6.2 U14.10 U14.11 U14.12
BOARD_RESETN: C10.1 J16.9 R29.2 R51.2 R52.1 U1.B1
CDC_S0: J7.1 R74.2 U5.2
CDC_S1_SDA: J8.1 J18.1 R73.2 U5.13
CDC_S2_SCL: J11.1 J19.1 R72.2 U5.12
CDC_VDD: C31.1 FB4.1 U5.3
CDC_XIN: C25.2 R66.1 U5.1 Y1.3(XO)
CDC_XOUT: C26.2 R66.2 U5.14 Y1.1
CDC_Y1: R67.2 U5.11
CT: C22.1 U3.4
DP_AUXN: C82.2 J9.17 R27.2
DP_AUXP: C81.2 J9.15 R113.1
DP_ML0N: C79.2 J9.3
DP_ML0P: C80.2 J9.1
DP_ML1N: C77.2 J9.6
DP_ML1P: C78.2 J9.4
DP_ML2N: C75.2 J9.9
DP_ML2P: C76.2 J9.7
DP_ML3N: C73.2 J9.12
DP_ML3P: C74.2 J9.10
DPTX_CAD: J9.13 R36.2
DPTX_GND: C83.1 J9.21 J9.22 J9.23 J9.24 R33.2
DSI_A0N: J4.35 R9.1 U1.J3
DSI_A0P: J4.33 R8.1 U1.H3
DSI_A1N: J4.27 R11.1 U1.J4
DSI_A1P: J4.25 R10.1 U1.H4
DSI_A2N: J4.11 R13.1 U1.J6
DSI_A2P: J4.9 R12.1 U1.H6
DSI_A3N: J4.3 R15.1 U1.J7
DSI_A3P: J4.1 R14.1 U1.H7
DSI_ACLKN: J4.19 R7.1 U1.J5
DSI_ACLKP: J4.17 R6.1 U1.H5
DSI_B0N: J4.36 U1.C1
DSI_B0P: J4.34 U1.C2
DSI_B1N: J4.28 U1.D1
DSI_B1P: J4.26 U1.D2
DSI_B2N: J4.12 U1.F1
DSI_B2P: J4.10 U1.F2
DSI_B3N: J4.4 U1.G1
DSI_B3P: J4.2 U1.G2
DSI_BCLKN: J4.20 U1.E1
DSI_BCLKP: J4.18 U1.E2
EDP_AUXN: C72.2 J6.35 R114.2
EDP_AUXP: C71.2 J6.33 R115.1
EDP_BL_ENABLE: J6.22 R186.1
EDP_BL_ENABLE_R: R186.2 U11.3
EDP_BL_PWR: J6.34 J6.36 J6.38 J6.40 J20.1
EDP_LCD_VCC: J6.10 J6.12 J21.1
EDP_ML0N: C69.2 J6.25
EDP_ML0P: C70.2 J6.27
EDP_ML1N: C67.2 J6.17
EDP_ML1P: C68.2 J6.19
EDP_ML2N: C65.2 J6.9
EDP_ML2P: C66.2 J6.11
EDP_ML3N: C63.2 J6.1
EDP_ML3P: C64.2 J6.3
EDP_PWM_DIM: J6.24 R187.1
EDP_PWM_DIM_R: R187.2 U12.3
EDP_SELF_TEST: J6.14 R192.1
EN1P2: C43.1 R79.2 U8.11
EN1P8: C47.1 R87.2 U9.11
EXT_REFCLK: J17.1 R105.1
FB_1PT2V: R82.1 R84.2 U8.16
FB_1PT8V: R89.1 R90.2 U9.16
FX_CLKN: J1.27 R7.2
FX_CLKP: J1.29 R6.2
FX_N0: J1.3 R9.2
FX_N1: J1.9 R11.2
FX_N2: J1.15 R13.2
FX_N3: J1.21 R15.2
FX_P0: J1.5 R8.2
FX_P1: J1.11 R10.2
FX_P2: J1.17 R12.2
FX_P3: J1.23 R14.2
GPIO1: J16.1 R54.1 SW2.16 U1.A4
GPIO2: J16.2 R55.1 SW2.15 U1.A5
GPIO3: J16.3 R56.1 SW2.14 U1.A6 U11.4
GPIO4: J16.4 R57.1 SW2.13 U1.B4 U12.4
HPD: J6.16 J9.18 J16.8 R111.1
I2C_3V3EN: R61.1 SW2.9(B8) U6.6
I2C_SCL: J1.4 J4.40 J16.7 J19.2 R3.2 R76.1 U1.H1
I2C_SCL_3P3V: J10.1 R77.2 R117.2 U6.1 U13.4
I2C_SDA: J1.6 J4.39 J16.6 J18.2 R4.2 R75.1 U1.J1
I2C_SDA_3P3V: J10.3 R78.2 R116.2 U6.8 U13.6
IRQ: R16.2 R70.2 TP1.1(TP) U1.A3 U2.2
IRQ_LED: D1.1 R2.1
IRQ_OUT: R1.2 R2.2 U2.4(Y)
LED9V: D3.1 R81.1
ML0N: C69.1 C79.1 U1.F9
ML0P: C70.1 C80.1 U1.F8
ML1N: C67.1 C77.1 U1.E9
ML1P: C68.1 C78.1 U1.E8
ML2N: C65.1 C75.1 U1.C9
ML2P: C66.1 C76.1 U1.C8
ML3N: C63.1 C73.1 U1.B9
ML3P: C64.1 C74.1 U1.B8
PG: R80.1 R88.1 R103.1 U4.1
PG1P2: R80.2 U8.9
PG1P8: R88.2 U9.9
PG3P3: R83.1 U14.4
PWRIN_SW: D8.1(C) SW6.1
REFCLK: C55.1 R67.1 R104.1
RESET#: R52.2 U3.1
RHPD: R5.1 R111.2 U1.J8
RREFCLK: R104.2 R105.2 U1.A7
SS1P2: C44.1 U8.15(SS)
SS1P8: C48.1 U9.15(SS)
SS_TR: C40.1 U14.9
SWOUT: L1.1 U14.1 U14.2 U14.3
TEST1: R59.1 SW2.11 U1.B3
TEST2: R60.1 SW2.10 U1.B5
TSL_A0: R188.2 R189.1 U13.2
TSL_INT: R191.1 U13.5
N16337340: U3.3 U4.4(Y)
N16337368: C24.1 R53.2 SW1.3(B_) SW1.4 U4.2
N16553551: J4.38 R70.1
N16649721: J4.37 R29.1
N16727318: D6.1 R101.1
N16746732: J9.20 R112.1
N16749444: J6.4 R116.1
N16749448: J6.2 R117.1
N16759353: J14.2 R86.2 U14.13
N16817438: J1.10 R16.1

Pads without a net: J1 12 16 18 22 24 28 30; J6 18 20 26 28; J10 4 5 6 7 8 9; NOREF 1; NOREF#5 1; NOREF#9 1; NOREF#21 1; NOREF#27 1; NOREF#28 1; NOREF#32 1; NOREF#33 1; SW6 3; U2 1; U5 4 8 9; XC17 2

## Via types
v1: diameter 0.254, hole 0.127, TOP to BOTTOM, 44 vias
v2: diameter 0.406, hole 0.203, TOP to BOTTOM, 359 vias
v3: diameter 0.33, hole 0.152, TOP to BOTTOM, 3 vias
v4: diameter 0.584, hole 0.305, TOP to BOTTOM, 3 vias

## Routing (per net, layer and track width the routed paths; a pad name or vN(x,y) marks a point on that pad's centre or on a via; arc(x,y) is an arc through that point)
GND: length 555.6
  TOP w0.178: U1.F4 36.58,46.4 36.44,46.54 v1(36.44,46.56) ; U1.A8 38.8,49.39 v1(38.86,49.45) ; v1(36.6,47.35) 36.6,47.1 U1.E4 ; U1.F5 37.3,46.19 v1(37.04,45.93)
  TOP w0.203: v1(36.88,47.62) 36.94,47.56 36.94,47.26 37.3,46.91 U1.E5 ; v1(37.69,45.93) 37.8,46.04 U1.F6 ; v1(38.31,47.32) 38.39,47.4 U1.D8 ; U1.G8 38.34,45.9 v1(38.32,45.92)
  TOP w0.254: v2(69.67,41.78) 69.38,41.5 J6.30 ; v2(9.57,46.86) 11.13,46.86 J4.21 ; J4.23 11.13,47.36 9.76,47.36 v2(9.56,47.56) ; J4.24 3.94,47.37 v2(3.75,47.56) ; J4.16 4,44.37 v2(3.78,44.58) ; J6.8 v2(66.16,50) ; J4.22 3.71,46.87 v2(3.71,46.86) ; v2(3.71,49.86) 3.71,49.87 J4.30 ; v2(60.43,50.28) 60.65,50.5 J6.5 ; J4.8 5.39,41.36 3.93,41.36 v2(3.75,41.55) ; J6.15 v2(63.81,47) ; J6.21 v2(60.49,44.5) ; J4.14 3.71,43.87 v2(3.71,43.86) ; J4.32 3.93,50.37 v2(3.74,50.56) ; v2(9.58,41.58) 9.8,41.36 11.13,41.36 J4.7 ; J6.6 v2(69.56,50.5) ; J6.7 v2(63.8,50) ; J4.13 11.13,43.86 v2(9.57,43.86) ; v2(60.45,38.33) 60.62,38.5 J6.37 ; J6.32 v2(69.65,41) ; J6.13 v2(60.35,47.5) ; J6.39 v2(63.79,38) ; v2(9.58,49.86) 9.58,49.86 11.13,49.86 J4.29 ; J6.31 v2(63.79,41) ; U12.2 v2(50.16,63.58) ; v2(3.71,40.86) 5.39,40.86 J4.6 ; J6.23 v2(63.81,44) ; v2(9.58,44.57) 9.79,44.36 11.13,44.36 J4.15 ; J6.29 v2(60.45,41.5) ; J4.31 11.13,50.36 9.77,50.36 v2(9.57,50.56) ; v2(9.58,40.86) 11.13,40.86 J4.5 ; U11.5 v2(46.35,59.59) ; U6.2 v2(75.59,94.69) ; U12.5 v2(50.16,59.64) ; U11.2 v2(46.35,63.53)
  TOP w0.305: v2(24.02,55.55) 23.98,55.6 23.21,55.6 C61.2 ; C62.2 v2(29.29,83.79)
  TOP w0.356: v2(8.29,100.83) 8.27,100.81 U3.2 ; C48.2 v2(39.72,70.26) ; U2.3 51.34,32.41 51.34,32.4 v2(51.34,32.34) ; C87.2 v2(51.77,65.2) ; C45.2 v2(32.42,60.22) ; C45.2 v2(34.96,60.22) ; C45.2 v2(33.72,59.39) ; R90.1 v2(37.29,73.65) ; C22.2 v2(2.26,100.7) ; C47.2 v2(40.79,63.93) ; C46.2 v2(31.79,74.75) ; C46.2 32.95,73.79 v2(32.97,73.81) ; C46.2 v2(30.45,73.79) ; C83.2 v2(83.62,62.61) ; U9.4 v2(31.14,66.41) ; C39.2 v2(44.19,72.1) ; C39.2 v2(42.84,71.21) ; C39.2 v2(41.58,72.1) ; R84.1 v2(43.71,84.36) ; SW2.3 v2(20.83,67.26) ; v2(3.96,81.58) 3.96,79.58 SW1.2 3.89,77.5 v2(3.88,77.5) ; C88.2 v2(51.64,57.35) ; U8.14 v2(43.79,79.23) ; C85.2 v2(47.01,66) ; v2(37.01,77.93) U8.4 ; J6.G2 64.86,47.85 v2(64.26,47.85) ; J6.G2 J6.G1 v2(64.14,52.81) ; J6.G2 J6.G3 ; U8.12 v2(43.81,77.93) ; v2(18.29,67.32) 18.29,67.32 SW2.1 ; U9.17 v2(35.65,70.51) ; SW2.4 v2(22.1,67.32) ; C9.2 54.66,35.23 54.69,35.27 v2(54.69,35.24) ; C24.2 v2(4.55,89.55) ; U13.3 v2(74.18,101.97) ; U8.17 41.09,81.99 v2(41.09,81.99) ; U8.3 v2(37.01,78.58) ; U9.14 v2(38.53,67.71) ; SW2.5 v2(23.37,67.26) ; v2(37.47,86.2) C42.2 v2(36.26,85.24) ; C23.2 v1(3.99,98.78) ; SW2.2 19.41,68.22 19.41,67.34 v2(19.38,67.31) ; U9.2 v2(31.29,67.71) ; R188.1 v2(71.12,105.54) ; v2(7.51,95.42) 7.51,95.42 U4.3 ; SW2.6 v2(24.64,67.28) ; D1.2 v2(53.59,28.14) ; U9.3 v2(31.34,67.06) ; D6.2 v2(40.13,88.92) ; U9.13 v2(38.51,67.06) ; U8.2 v2(36.98,79.23) ; C44.2 v2(44.99,81.64) ; SW2.8 v2(27.18,67.15) ; J6.G3 64.24,41.57 v2(64.23,41.57) ; J6.G3 J6.G4 64.93,36.67 v2(64.93,34.9) ; v2(3.9,75.03) 3.89,75.02 SW1.1 v2(3.89,70.95) ; U8.13 v2(43.81,78.58) ; R33.1 v2(88.9,62.59) ; U9.12 v2(38.48,66.41) ; R192.2 v2(72.26,46.79) ; C86.2 v2(47.75,57.35) ; SW2.7 v2(25.91,67.15) ; C43.2 v2(46.07,75.34) ; R115.2 v2(58.24,40.39)
  TOP w0.508: v2(8.28,36.47) 8.28,38.54 J4.G1 8.28,38.57 v2(8.28,40.61) 8.28,43.43 J4.G2 8.26,46.66 v2(8.28,46.68) 8.28,49.78 J4.G3 J4.G4 8.27,54.69 8.27,56.37 v2(8.28,56.38)
  L2_GND w0.356: 34.33,8.2 J1.8 ; J1.8 35.2,7.33 ; J1.8 35.2,9.08 ; J1.8 36.08,8.2 ; J1.2 43.7,8.2 ; J1.2 42.82,7.33 ; J1.2 42.82,9.08 ; J1.2 41.95,8.2 ; 11.47,10.74 J1.25 ; J1.25 12.34,9.87 ; J1.25 12.34,11.62 ; J1.25 13.22,10.74 ; 26.71,8.2 J1.14 ; J1.14 27.58,7.33 ; J1.14 28.46,8.2 ; J1.14 27.58,9.08 ; 3.85,10.74 J1.31 ; J1.31 5.6,10.74 ; J1.31 4.72,9.87 ; J1.31 4.72,11.62 ; J1.13 28.46,10.74 ; J1.13 27.58,11.62 ; J1.13 27.58,9.87 ; J1.13 26.71,10.74 ; J1.32 4.72,9.08 ; J1.32 4.72,7.33 ; J1.32 3.85,8.2 ; J1.32 5.6,8.2 ; 34.33,10.74 J1.7 ; J1.7 35.2,9.87 ; J1.7 35.2,11.62 ; J1.7 36.08,10.74 ; 19.09,10.74 J1.19 ; J1.19 19.96,9.87 ; J1.19 19.96,11.62 ; J1.19 20.84,10.74 ; 39.37,91.2 J14.1 ; J14.1 40.25,92.08 ; J14.1 39.37,92.95 ; J14.1 38.49,92.08 ; 19.09,8.2 J1.20 ; J1.20 19.96,7.33 ; J1.20 20.84,8.2 ; J1.20 19.96,9.08 ; 47.64,99.19 U14.17 ; U14.17 48.13,98.71 ; U14.17 48.13,99.68 ; 11.47,8.2 J1.26 ; J1.26 12.34,9.08 ; J1.26 12.34,7.33 ; J1.26 13.22,8.2 ; 42.82,9.87 J1.1 ; J1.1 42.82,11.62 ; J1.1 43.7,10.74 ; J1.1 41.95,10.74
  L2_GND w0.864: TP5.1 67.48,74.89 ; TP5.1 66.6,74.01 ; TP5.1 67.48,73.14 ; TP5.1 68.35,74.01 ; 11.49,69.51 LP4.1 ; LP4.1 12.71,70.73 ; LP4.1 13.93,69.51 ; LP4.1 12.71,68.3 ; J17.2 41.04,31.53 ; J17.2 39.28,31.53 ; J17.2 40.16,30.66 ; J17.2 40.16,32.41 ; J8.2 52.52,81.87 ; J8.2 51.45,82.93 ; J8.2 50.38,81.87 ; J8.2 51.45,80.8 ; 12.2,105.99 J13.2 ; J13.2 14.28,103.9 ; J13.2 16.37,105.99 ; J13.2 14.28,108.07 ; J19.3 60.91,85.41 ; J19.3 60.04,84.53 ; J19.3 60.91,83.66 ; J19.3 61.79,84.53 ; 19.08,107.16 J13.3 ; J13.3 21.17,109.24 ; J13.3 17,109.24 ; J13.3 19.08,111.32 ; 53.66,84.53 J18.3 ; J18.3 55.41,84.53 ; J18.3 54.53,85.41 ; J18.3 54.53,83.65 ; 33.03,87.54 J16.10 ; J16.10 32.15,88.42 ; J16.10 33.9,88.42 ; J16.10 33.03,89.29 ; J10.10 59.23,113.85 ; J10.10 59.23,112.1 ; J10.10 60.11,112.97 ; J10.10 58.35,112.97 ; 39.68,110.45 LP5.1 ; LP5.1 40.9,109.23 ; LP5.1 42.12,110.45 ; LP5.1 40.9,111.67 ; 48.19,112.97 J10.2 ; J10.2 49.95,112.97 ; J10.2 49.07,112.1 ; J10.2 49.07,113.85 ; 75.67,111.74 TP6.1 ; TP6.1 76.54,110.86 ; TP6.1 76.54,112.61 ; TP6.1 77.42,111.74 ; J7.2 49.43,81.86 ; J7.2 47.29,81.86 ; J7.2 48.36,82.93 ; J7.2 48.36,80.79 ; 56.52,81.8 J11.2 ; J11.2 57.59,82.86 ; J11.2 57.59,80.73 ; J11.2 58.66,81.8
  L3_SIG w0.356: 42.82,9.87 J1.1 ; J1.1 43.7,10.74 ; J1.1 42.82,11.62 ; J1.1 41.95,10.74 ; U14.17 48.13,99.68 ; U14.17 47.64,99.19 ; U14.17 48.13,98.71 ; 3.85,8.2 J1.32 ; J1.32 5.6,8.2 ; J1.32 4.72,7.33 ; J1.32 4.72,9.08 ; J1.13 28.46,10.74 ; J1.13 27.58,11.62 ; J1.13 27.58,9.87 ; J1.13 26.71,10.74 ; J1.20 19.96,9.08 ; J1.20 19.09,8.2 ; J1.20 20.84,8.2 ; J1.20 19.96,7.33 ; J1.31 5.6,10.74 ; J1.31 4.72,9.87 ; J1.31 4.72,11.62 ; J1.31 3.85,10.74 ; 35.2,9.87 J1.7 ; J1.7 36.08,10.74 ; J1.7 34.33,10.74 ; J1.7 35.2,11.62 ; 38.49,92.08 J14.1 ; J14.1 39.37,92.95 ; J14.1 39.37,91.2 ; J14.1 40.25,92.08 ; 34.33,8.2 J1.8 ; J1.8 35.2,9.08 ; J1.8 35.2,7.33 ; J1.8 36.08,8.2 ; J1.26 12.34,9.08 ; J1.26 12.34,7.33 ; J1.26 13.22,8.2 ; J1.26 11.47,8.2 ; 19.96,9.87 J1.19 ; J1.19 20.84,10.74 ; J1.19 19.09,10.74 ; J1.19 19.96,11.62 ; 26.71,8.2 J1.14 ; J1.14 27.58,7.33 ; J1.14 28.46,8.2 ; J1.14 27.58,9.08 ; J1.25 13.22,10.74 ; J1.25 12.34,11.62 ; J1.25 12.34,9.87 ; J1.25 11.47,10.74 ; 42.82,7.33 J1.2 ; J1.2 42.82,9.08 ; J1.2 41.95,8.2 ; J1.2 43.7,8.2
  L3_SIG w0.864: J10.10 60.11,112.97 ; J10.10 58.35,112.97 ; J10.10 59.23,112.1 ; J10.10 59.23,113.85 ; J13.3 19.08,111.32 ; J13.3 19.08,107.16 ; J13.3 17,109.24 ; J13.3 21.17,109.24 ; 54.53,83.65 J18.3 ; J18.3 53.66,84.53 ; J18.3 54.53,85.41 ; J18.3 55.41,84.53 ; 33.03,87.54 J16.10 ; J16.10 33.9,88.42 ; J16.10 33.03,89.29 ; J16.10 32.15,88.42 ; J19.3 61.79,84.53 ; J19.3 60.91,83.66 ; J19.3 60.04,84.53 ; J19.3 60.91,85.41 ; 11.49,69.51 LP4.1 ; LP4.1 12.71,70.73 ; LP4.1 13.93,69.51 ; LP4.1 12.71,68.3 ; LP5.1 40.9,111.67 ; LP5.1 42.12,110.45 ; LP5.1 39.68,110.45 ; LP5.1 40.9,109.23 ; TP6.1 77.42,111.74 ; TP6.1 76.54,110.86 ; TP6.1 75.67,111.74 ; TP6.1 76.54,112.61 ; 49.07,112.1 J10.2 ; J10.2 49.07,113.85 ; J10.2 48.19,112.97 ; J10.2 49.95,112.97 ; J8.2 52.52,81.87 ; J8.2 50.38,81.87 ; J8.2 51.45,80.8 ; J8.2 51.45,82.93 ; J7.2 48.36,82.93 ; J7.2 48.36,80.79 ; J7.2 47.29,81.86 ; J7.2 49.43,81.86 ; 66.6,74.01 TP5.1 ; TP5.1 67.48,73.14 ; TP5.1 68.35,74.01 ; TP5.1 67.48,74.89 ; J17.2 41.04,31.53 ; J17.2 39.28,31.53 ; J17.2 40.16,32.41 ; J17.2 40.16,30.66 ; 57.59,80.73 J11.2 ; J11.2 57.59,82.86 ; J11.2 58.66,81.8 ; J11.2 56.52,81.8 ; J13.2 16.37,105.99 ; J13.2 14.28,108.07 ; J13.2 14.28,103.9 ; J13.2 12.2,105.99
  L5_GND w0.356: J1.26 13.22,8.2 ; J1.26 11.47,8.2 ; J1.26 12.34,9.08 ; J1.26 12.34,7.33 ; J1.14 27.58,9.08 ; J1.14 28.46,8.2 ; J1.14 27.58,7.33 ; J1.14 26.71,8.2 ; J1.25 13.22,10.74 ; J1.25 12.34,9.87 ; J1.25 11.47,10.74 ; J1.25 12.34,11.62 ; 35.2,7.33 J1.8 ; J1.8 35.2,9.08 ; J1.8 34.33,8.2 ; J1.8 36.08,8.2 ; 47.64,99.19 U14.17 ; U14.17 48.13,98.71 ; U14.17 48.13,99.68 ; J1.32 4.72,9.08 ; J1.32 3.85,8.2 ; J1.32 5.6,8.2 ; J1.32 4.72,7.33 ; 19.96,9.87 J1.19 ; J1.19 19.96,11.62 ; J1.19 20.84,10.74 ; J1.19 19.09,10.74 ; 19.96,7.33 J1.20 ; J1.20 19.09,8.2 ; J1.20 19.96,9.08 ; J1.20 20.84,8.2 ; J1.7 36.08,10.74 ; J1.7 34.33,10.74 ; J1.7 35.2,9.87 ; J1.7 35.2,11.62 ; 4.72,9.87 J1.31 ; J1.31 3.85,10.74 ; J1.31 5.6,10.74 ; J1.31 4.72,11.62 ; 41.95,10.74 J1.1 ; J1.1 42.82,9.87 ; J1.1 43.7,10.74 ; J1.1 42.82,11.62 ; 42.82,7.33 J1.2 ; J1.2 43.7,8.2 ; J1.2 42.82,9.08 ; J1.2 41.95,8.2 ; 38.49,92.08 J14.1 ; J14.1 39.37,92.95 ; J14.1 39.37,91.2 ; J14.1 40.25,92.08 ; 26.71,10.74 J1.13 ; J1.13 28.46,10.74 ; J1.13 27.58,11.62 ; J1.13 27.58,9.87
  L5_GND w0.864: 12.71,68.3 LP4.1 ; LP4.1 13.93,69.51 ; LP4.1 11.49,69.51 ; LP4.1 12.71,70.73 ; J19.3 60.91,85.41 ; J19.3 61.79,84.53 ; J19.3 60.91,83.66 ; J19.3 60.04,84.53 ; J8.2 51.45,82.93 ; J8.2 52.52,81.87 ; J8.2 51.45,80.8 ; J8.2 50.38,81.87 ; 76.54,110.86 TP6.1 ; TP6.1 77.42,111.74 ; TP6.1 75.67,111.74 ; TP6.1 76.54,112.61 ; J7.2 48.36,82.93 ; J7.2 49.43,81.86 ; J7.2 48.36,80.79 ; J7.2 47.29,81.86 ; 57.59,80.73 J11.2 ; J11.2 58.66,81.8 ; J11.2 56.52,81.8 ; J11.2 57.59,82.86 ; J18.3 54.53,85.41 ; J18.3 55.41,84.53 ; J18.3 54.53,83.65 ; J18.3 53.66,84.53 ; 39.68,110.45 LP5.1 ; LP5.1 40.9,109.23 ; LP5.1 42.12,110.45 ; LP5.1 40.9,111.67 ; 12.2,105.99 J13.2 ; J13.2 14.28,108.07 ; J13.2 14.28,103.9 ; J13.2 16.37,105.99 ; J17.2 40.16,32.41 ; J17.2 40.16,30.66 ; J17.2 41.04,31.53 ; J17.2 39.28,31.53 ; 32.15,88.42 J16.10 ; J16.10 33.9,88.42 ; J16.10 33.03,87.54 ; J16.10 33.03,89.29 ; J10.2 49.95,112.97 ; J10.2 49.07,112.1 ; J10.2 49.07,113.85 ; J10.2 48.19,112.97 ; J13.3 19.08,111.32 ; J13.3 17,109.24 ; J13.3 21.17,109.24 ; J13.3 19.08,107.16 ; 66.6,74.01 TP5.1 ; TP5.1 67.48,73.14 ; TP5.1 67.48,74.89 ; TP5.1 68.35,74.01 ; 58.35,112.97 J10.10 ; J10.10 59.23,113.85 ; J10.10 60.11,112.97 ; J10.10 59.23,112.1
  BOTTOM w0.203: 82.01,46.49 v2(82.02,46.48) ; 82.01,44.99 v2(82.01,44.99)
  BOTTOM w0.254: U5.5 47.06,24.03 v2(47.05,24.04) ; C56.2 38.74,45.92 v1(38.32,45.92) ; v1(36.12,43.01) 35.93,43.21 C59.2 ; J9.11 v2(82.03,49.49) ; C10.2 v1(34.49,49.39) ; J9.14 v2(82.22,50.99) ; v2(37.03,51.23) 36.93,51.13 C6.2 ; v2(35.81,54.76) 35.81,54.04 C1.2 ; J9.19 v2(78.63,53.49) ; J9.2 82.01,44.99 ; C58.2 v1(34.42,50.17) ; v1(36.88,47.62) 36.9,47.64 36.9,47.64 36.77,47.77 C3.2 ; v1(38.3,46.89) 38.24,46.84 C5.2 ; C4.2 36.27,50.85 36.53,51.1 36.53,51.74 v2(36.73,51.94) ; J9.5 82.01,46.49 ; J9.16 v2(78.67,51.99) ; C60.2 v1(40.13,50.65) ; C8.2 v2(41.71,47.27) ; C84.2 v2(36.6,52.66) ; U5.10 v2(41.32,24.03) ; C7.2 41.2,44.12 v2(41.63,43.69) ; C89.2 v2(75.49,104.6) ; J9.8 v2(82.05,47.99)
  BOTTOM w0.356: R113.2 v2(75.77,51.49) ; C55.2 38.08,23.66 v2(38.08,23) ; C25.1 48.89,27.8 v2(48.9,27.81) ; Y1.2 v2(46.73,31.6) ; v2(30.8,47.37) 30.8,47.01 31.31,46.61 31.5,46.61 ; C30.2 73.47,93.21 v2(73.58,93.32) ; C90.2 42.32,46.63 42.62,46.94 v2(42.62,47.27) ; C27.2 v2(49.96,19.14) ; v2(30.1,45.97) 30.86,45.97 31.5,46.61 ; 31.5,46.61 C57.2 ; Y1.4 v2(46.39,29.95) ; C11.2 42.76,44.92 v2(42.77,44.91) ; v2(42.7,29.77) 42.7,29.76 C26.1 ; C28.2 79.37,93.02 79.4,92.99 v2(79.4,92.94) ; C32.2 v2(49.37,19.44) ; C33.2 v2(48.26,19.55) ; R36.1 v2(74.3,56.82) ; C29.2 v2(75.62,96.52) ; C91.2 42.59,45.86 v2(42.77,46.05) ; C31.2 v2(51.6,23.14) ; R5.2 v2(38.23,42.45)
  BOTTOM w0.381: C2.2 35.33,41.82 v1(35.33,41.23)
  vias: v2(30.73,100.84) v2(30.72,32.24) v2(31.5,100.84) v2(33.34,76.58) v2(33.53,27.69) v2(33.87,68.17) v2(33.87,67.4) v2(33.87,66.64) v2(33.87,65.88) v2(34.57,77.67) v2(34.63,68.17) v2(34.63,65.88) v2(35.4,68.17) v2(35.4,65.88) v2(35.81,76.58) v2(36.16,68.17) v2(36.16,67.4) v2(36.16,66.64) v2(36.16,65.88) v2(37.11,30.63) v2(39.39,79.63) v2(39.39,78.87) v2(39.39,78.1) v2(39.39,77.34) v2(40.06,37.31) v2(40.15,79.63) v2(40.15,77.34) v2(40.28,96.19) v2(40.89,96.19) v2(40.91,79.63) v2(40.91,77.34) v2(41.53,96.19) v2(41.67,79.63) v2(41.67,78.87) v2(41.67,78.1) v2(41.67,77.34) v2(42.14,96.22) v2(42.95,94.84) v2(43.56,94.84) v2(44.02,34.83) v2(44.15,94.84) v2(44.22,102.72) v2(44.73,94.84) v2(44.81,102.72) v2(45.33,39.92) v2(47.24,93.98) v2(47.27,93.37) v2(47.27,92.74) v2(58.75,46.69) v2(58.75,44.81) v2(58.78,43.74) v2(58.78,41.76) v2(58.95,53.52) v2(59.63,50.2) v2(59.7,47.29) v2(60.24,53.54) v4(47.12,100.2) v4(47.12,99.19) v4(48.13,100.2)
VCC: length 10.8
  TOP w0.152: U1.J2 35.8,44.15 35.28,43.63 v2(35.28,43.56)
  TOP w0.178: U1.D5 v1(37.3,47.87) ; U1.J9 39.3,44.65 v2(39.67,44.27) ; v1(38.2,47.8) U1.D6
  L4_PWR w0.356: LP3.1 46.35,53.29 ; LP3.1 47.57,52.07 ; LP3.1 45.14,52.07 ; LP3.1 46.35,50.85
  BOTTOM w0.254: v1(37.3,47.87) 37.33,47.9 C3.1 ; C5.1 v1(38.2,47.8)
  BOTTOM w0.305: C7.1 39.83,44.12 v2(39.67,44.27)
  BOTTOM w0.381: v2(35.28,43.56) 35.28,42.91 C2.1
VCCA: length 15.4
  TOP w0.076: v1(35.43,49.3) 35.43,49.29 35.55,49.17 35.55,48.65 U1.B2 ; v2(35.33,44.3) 35.55,44.52 35.55,45.15 U1.H2
  TOP w0.152: U1.G9 39.33,45.87 39.51,45.87 39.66,45.72 40.03,45.72 v2(40.31,45.44) ; v1(38.29,46.41) U1.E6
  TOP w0.203: v2(39.5,49.5) 39.3,49.31 U1.A9
  L4_PWR w0.356: 24.05,51.33 LP9.1 ; LP9.1 26.49,51.33 ; LP9.1 25.27,50.11 ; LP9.1 25.27,52.55
  BOTTOM w0.254: v1(38.29,46.41) 38.3,46.41 C56.1 ; C58.1 35.28,49.3 v1(35.43,49.3) ; v2(35.33,44.3) 35.38,44.25 35.75,44.25 C59.1 ; C60.1 39.52,49.48 v2(39.5,49.5)
  BOTTOM w0.356: v2(31.75,49.43) C57.1 31.22,48.64 30.94,48.92 v2(30.94,49.45) ; v2(40.31,45.44) 40.32,45.45 C11.1
VCCIO: length 23.4
  TOP w0.076: U1.B6 37.8,48.4 37.55,48.65 37.55,49.17 37.49,49.23 37.49,49.88 ; U1.A2 35.76,49 35.74,49.06 35.74,49.53 v1(35.46,49.81)
  TOP w0.203: 37.49,49.88 v1(37.49,50.16)
  TOP w0.254: v1(37.49,50.16) 37.49,51.77 37.39,51.87
  TOP w0.356: 40.04,56.13 v1(40.04,53.09) 39.86,53.26 37.87,53.26 37.39,52.78 37.39,51.87 ; 40.04,56.13 R108.1 ; 40.04,56.13 LP2.1
  BOTTOM w0.203: C4.1 35.94,50.29 v1(35.46,49.81)
  BOTTOM w0.254: v1(37.49,50.16) 37.44,50.11 C6.1 36.58,50.11 36.4,50.29 C4.1 36.05,50.31 35.92,50.31 35.28,50.95 35.28,51.38 C1.1
  BOTTOM w0.381: v1(40.04,53.09) 40.04,51.73 40.79,50.98 40.79,48.62 R118.1
VDDPLL: length 5.2
  TOP w0.178: U1.D9 39.51,47.4 39.64,47.27 v2(40.01,47.27)
  BOTTOM w0.254: 40.23,46.63 C90.1 ; C8.1 v2(40.01,47.27)
  BOTTOM w0.356: R118.2 40.03,47.29 v2(40.01,47.27) 40.03,47.24 40.03,46.84 40.23,46.63 40.23,46.08 40.36,45.95 40.88,45.95 C91.1
A1_SCL: length 1
  TOP w0.254: R76.2 74.56,93.69 U6.4
A1_SDA: length 1
  TOP w0.254: R75.2 77.36,92.81 U6.5
ADDR: length 50.4
  TOP w0.076: 34.4,49.78 34.59,49.78 34.87,49.5 34.87,49.33 U1.A1
  TOP w0.203: 34.4,49.78 33.88,49.78
  TOP w0.356: 33.88,49.78 33.58,50.09 31.39,50.09 30.35,51.13 30.35,53.86 28.75,55.46 28.75,69.29 v2(23.37,74.68) SW2.12 R58.1
  BOTTOM w0.356: J16.5 20.33,81.36 20.19,81.22 20.19,77.86 v2(23.37,74.68)
AMUX: length 8
  TOP w0.076: U1.B7 38.05,48.65 38.05,49.66 38.33,49.94
  TOP w0.254: v2(38.33,52.25) 38.33,49.94
  BOTTOM w0.356: v2(38.33,52.25) 37.9,52.68 C84.1 37.72,53.75 37.16,54.31 XC17.1
AUXN: length 18.9
  TOP w0.076: U1.H9 39.31,45.4
  TOP w0.127: 39.31,45.4 40.12,44.59 40.3,44.59 40.54,44.51 56.55,39.66 56.73,39.66 C82.1
AUXP: length 19.5
  TOP w0.076: 39.71,45.38 39.68,45.38 39.41,45.65 39.05,45.65 U1.H8
  TOP w0.127: C81.1 56.85,39.93 56.59,39.93 40.62,44.77 40.34,44.86 40.23,44.86 39.71,45.38
BOARD_1P2V: length 16.6
  TOP w0.305: LP7.1 32.4,83.19 C62.1 ; C61.1 23.54,56.2 v2(24,56.2)
  TOP w0.356: U8.1 v2(36.48,79.88) ; v2(38.35,81.48) 39.13,81.48 U8.20 ; U8.19 v2(39.79,81.97) ; v2(37.47,82.34) C42.1 v2(35.99,83.21) ; R82.2 v2(40.5,82.45) 40.44,82.39 U8.18
  BOTTOM w0.864: LP7.1 33.66,83.14 ; LP7.1 31.22,83.14 ; LP7.1 32.44,84.36 ; LP7.1 32.44,81.92
  vias: v2(24.69,56.01) v2(25.55,56.01) v2(44.65,60.76) v2(44.96,60.27)
BOARD_1P8V: length 41.8
  TOP w0.254: U6.3 v2(73.53,94.19) ; U12.6 v2(50.82,59.64)
  TOP w0.356: U9.18 v2(35,70.56) ; C23.1 3.77,99.8 v2(3.84,99.86) U3.6 ; v2(2.35,95.41) 2.35,95.41 R103.2 ; C9.1 53.55,35.78 53.55,35.79 v2(53.55,35.85) ; C88.1 50.78,59.61 v2(50.82,59.64) ; R56.2 v2(20.83,79.38) ; R51.1 v2(9.76,100.53) ; v2(33.71,70.54) 33.7,70.53 U9.20 ; R4.1 v2(15.57,56.69) ; C86.1 46.97,59.47 47.01,59.5 v2(47.01,59.59) U11.6 ; R60.2 v1(25.91,79.37) ; R58.2 v2(23.37,79.44) ; R59.2 v2(24.64,79.38) ; v2(35.04,72.43) 35.03,72.42 R89.2 ; v2(54.43,34.26) 54.42,34.26 U2.5 ; R108.2 43.46,56.62 v2(43.18,56.9) ; U4.5 v2(5.58,98.53) ; R3.1 v2(14.81,59.55) ; U9.1 v2(31.32,68.36) ; R57.2 v2(22.1,79.45) ; C46.1 v2(30.42,71.76) ; R53.1 v2(4.62,92.26) ; U3.5 v2(3.84,100.81) ; R55.2 v2(19.56,79.38) ; U9.19 v2(34.35,70.54) ; R54.2 v2(18.29,79.41)
  L4_PWR w0.864: LP1.1 58.57,58.57 ; LP1.1 56.13,58.57 ; LP1.1 57.35,59.79 ; LP1.1 57.35,57.35
  BOTTOM w0.254: v2(47,23.34) 47.04,23.38 U5.6 ; v2(48.27,22.07) 48.27,22.02 48.29,22.04 U5.7 49.5,22.73 v2(49.5,22.73)
  BOTTOM w0.356: R74.1 v2(51.55,27.08) ; v2(39.58,26.35) 39.58,27.02 R73.1 ; C30.1 73.03,94.19 v2(73.53,94.19) ; C33.1 48.26,22.06 v2(48.27,22.07) ; C32.1 v2(49.37,22.05) ; v2(50.25,22.81) 50.25,22.88 50.25,22.89 FB4.2 ; C27.1 51.17,21.52 v2(50.6,22.09) ; R72.1 v2(37.32,26.79)
BOARD_3P3V: length 94.3
  TOP w0.254: U6.7 78.33,94.69 v2(78.38,94.74) ; C87.1 v2(50.82,63.53) 50.82,62.4 U12.1 ; U11.1 47.01,62.4 v2(47.01,63.53) C85.1 ; v2(46.86,97.18) 47.2,97.18 47.38,97.36 U14.14
  TOP w0.356: U9.10 v2(36.3,63.5) ; R79.1 v2(44.09,76.04) ; U8.5 37.53,77.28 v2(37.53,76.59) ; U8.6 39.13,75.4 v2(38.79,75.05) ; R78.1 78.89,94.31 78.84,94.36 v2(78.84,94.39) ; U9.8 v2(35,63.58) ; C45.1 32.56,62.26 v2(32.54,62.24) ; C45.1 34.9,62.26 v2(34.9,62.25) ; C45.1 33.72,63.09 v2(33.71,63.1) ; v2(33.03,64.16) 33.7,64.16 U9.6 ; U9.5 v2(31.32,65.76) ; R191.2 v2(79.76,104.65) ; R83.2 v2(57.15,101.6) ; v2(73.76,96.27) 73.71,96.32 R77.1 ; U8.7 v2(39.79,74.99) ; v2(56.98,31.78) 56.17,31.78 R1.1 ; R114.1 v2(58.24,39.09) ; U8.8 v2(40.44,75.18) ; v2(38.84,64.6) 38.84,64.59 R87.1 ; R61.2 v2(27.18,79.32) ; C39.1 v2(42.84,74.96) ; R189.2 v2(73.03,105.41) ; R101.2 39.31,83.13 39.31,82.5 v2(39.29,82.48) ; U13.1 v2(74.18,103.77) ; U8.10 v2(41.74,75.21) ; U9.7 v2(34.35,63.53)
  L4_PWR w0.356: 78.5,77.47 J21.2 ; J21.2 79.38,78.35 ; J21.2 79.38,76.59 ; J21.2 80.25,77.47
  L4_PWR w0.864: 59.49,92.63 LP6.1 ; LP6.1 59.49,95.07 ; LP6.1 60.71,93.85 ; LP6.1 58.27,93.85
  BOTTOM w0.254: C89.1 v2(74.93,104.65)
  BOTTOM w0.356: 57.04,37.35 58.24,38.56 v2(58.24,39.09) ; C28.1 v2(78.36,92.94) ; C29.1 v2(76.64,96.55) ; R27.1 R112.2
  BOTTOM w0.508: v2(76.56,67.92) 76.25,67.61 76.25,54.31 R112.2 ; v2(56.98,31.78) 57.04,31.83 57.04,37.35 55.45,38.94 v2(55.45,61.8)
BOARD_9V: length 12
  TOP w0.356: v2(31.11,108.58) R81.2 29.97,107.82 v2(29.84,107.95)
  L4_PWR w0.356: J20.2 36.83,101.21 ; J20.2 36.83,99.45 ; J20.2 35.95,100.33 ; J20.2 37.71,100.33
  L4_PWR w0.864: 29.85,112.67 SW6.2 ; SW6.2 31.81,112.67 ; SW6.2 30.83,111.69 ; SW6.2 30.83,113.64
  BOTTOM w0.356: R86.1 43.81,97.66 44.45,98.3 v2(45.09,98.3)
BOARD_RESETN: length 106.4
  TOP w0.254: U1.B1 v3(34.79,48.85) 34.1,48.85
  TOP w0.356: v2(27.46,51.46) 27.46,51.5 ; 27.46,51.5 26.75,52.21 26.75,57.78 19.31,65.21 16.79,65.21 15.83,66.17 15.83,73.43 11.34,77.91 11.34,80.79 ; 27.46,51.5 30.11,48.85 34.1,48.85 ; R29.2 v2(15.33,52.86) ; 11.34,80.79 7.9,84.24 7.9,89.82 9.76,91.69 9.76,96.93 9.76,96.93 R51.2 9.76,98.71 R52.1 ; 11.34,80.79 22.86,80.79 J16.9
  BOTTOM w0.254: v3(34.79,48.85) 34.77,48.83 C10.1
  BOTTOM w0.356: v2(15.33,52.86) 18.53,49.66 26.77,49.66 27.46,50.34 v2(27.46,51.46)
CDC_S0: length 61.5
  TOP w0.356: J7.1 48.36,69.75 50.22,67.89 54.04,67.89 v2(54.1,67.94)
  BOTTOM w0.254: U5.2 50.06,25.98 R74.2
  BOTTOM w0.356: v2(54.1,67.94) 54.1,38.91 52.63,37.44 52.63,30.39 50.41,28.17 R74.2
CDC_S1_SDA: length 65.5
  TOP w0.356: J18.1 54.41,79.33 J8.1 51.45,74.7 51.87,74.28 v2(51.87,69.97)
  BOTTOM w0.254: U5.13 41.62,25.98
  BOTTOM w0.356: v2(51.87,69.97) 52.96,68.88 52.96,41.29 41.23,29.55 40.36,29.55 39.59,28.78 R73.2 40.33,28.17 40.99,27.51 40.99,26.61 41.62,25.98
CDC_S2_SCL: length 73.7
  TOP w0.356: v2(57.64,74.29) 57.64,79.21 J11.1 57.79,79.45 J19.1
  BOTTOM w0.254: U5.12 41.32,25.33
  BOTTOM w0.356: 41.32,25.33 40.93,25.72 38.95,25.72 38.64,26.04 R72.2 38.48,35.53 39.26,36.32 43.45,36.32 49.4,42.27 49.4,69.76 51.32,71.67 55.02,71.67 v2(57.64,74.29)
CDC_VDD: length 3.4
  BOTTOM w0.254: U5.3 50.07,25.33 FB4.1
  BOTTOM w0.356: FB4.1 51.58,25.15 C31.1
CDC_XIN: length 9
  BOTTOM w0.254: 49.77,27.08 49.32,26.63 U5.1
  BOTTOM w0.356: Y1.3 48.12,29.44 C25.2 ; C25.2 48.15,28.84 49.16,28.84 49.77,28.24 49.77,27.08 ; C25.2 48.04,28.89 46.89,28.89 46,28 R66.1
CDC_XOUT: length 7.2
  BOTTOM w0.254: U5.14 42.69,28.05
  BOTTOM w0.356: Y1.1 44.44,30.53 R66.2 44.38,28.07 C26.2 42.69,28.05
CDC_Y1: length 2
  BOTTOM w0.254: U5.11 40.71,24.68
  BOTTOM w0.356: 40.71,24.68 R67.2
CT: length 1.9
  TOP w0.356: C22.1 3.74,101.72 3.79,101.76 U3.4
DP_AUXN: length 42.3
  TOP w0.127: C82.2 v2(57.61,38.79)
  BOTTOM w0.127: R27.2 77.81,52.49 J9.17 81.75,52.49 82.1,52.15 83.01,52.15 83.26,51.9 83.26,44.4 78.43,39.57 57.73,39.57 57.61,39.45 v2(57.61,38.79)
DP_AUXP: length 41.5
  TOP w0.127: v2(57.58,40.69) 57.56,40.67 C81.2
  BOTTOM w0.127: R113.1 80.39,51.49 J9.15 81.75,51.49 82.15,51.88 82.9,51.88 83,51.79 83,44.51 78.32,39.84 57.74,39.84 57.58,40 v2(57.58,40.69)
DP_ML0N: length 22.8
  TOP w0.127: v2(59.89,43.69) 59.36,43.69 C79.2
  BOTTOM w0.127: J9.3 79.25,45.49 78.91,45.15 77.28,45.15 75.02,42.89 60.14,42.89 59.89,43.14 v2(59.89,43.69)
DP_ML0P: length 22.8
  TOP w0.127: C80.2 v2(59.89,41.81)
  BOTTOM w0.127: J9.1 79.26,44.49 78.87,44.88 77.39,44.88 75.13,42.62 60.14,42.62 59.89,42.37 v2(59.89,41.81)
DP_ML1N: length 22.8
  TOP w0.127: v2(59.89,46.69) 59.36,46.69 C77.2
  BOTTOM w0.127: J9.6 79.25,46.99 78.88,46.62 74.01,46.62 72.52,45.14 65.76,45.14 65.02,45.87 60.12,45.87 59.89,46.1 v2(59.89,46.69)
DP_ML1P: length 22.8
  TOP w0.127: C78.2 v2(59.89,44.81)
  BOTTOM w0.127: J9.4 79.26,45.99 78.89,46.35 74.12,46.35 72.63,44.87 65.65,44.87 64.91,45.6 60.08,45.6 59.89,45.42 v2(59.89,44.81)
DP_ML2N: length 22.8
  TOP w0.127: C75.2 v2(59.91,49.66)
  BOTTOM w0.127: J9.9 79.25,48.49 78.8,48.04 72.27,48.04 70.75,49.57 66.87,49.57 66.22,48.92 60.08,48.92 59.91,49.08 v2(59.91,49.66)
DP_ML2P: length 22.8
  TOP w0.127: C76.2 v2(59.9,47.83)
  BOTTOM w0.127: J9.7 79.25,47.49 78.97,47.78 72.16,47.78 70.64,49.3 66.98,49.3 66.33,48.65 60.08,48.65 59.89,48.46 59.89,47.83 v2(59.9,47.83)
DP_ML3N: length 22.8
  TOP w0.127: C73.2 v2(59.92,52.7)
  BOTTOM w0.127: J9.12 79.25,49.99 78.89,49.63 73.66,49.63 71.39,51.9 60.16,51.9 59.92,52.15 v2(59.92,52.7)
DP_ML3P: length 22.8
  TOP w0.127: C74.2 59.36,50.83 v2(59.89,50.83)
  BOTTOM w0.127: v2(59.89,50.83) 59.89,51.36 60.17,51.64 71.28,51.64 73.55,49.36 78.91,49.36 79.28,48.99 J9.10
DPTX_CAD: length 10.4
  BOTTOM w0.203: J9.13 78.82,50.49
  BOTTOM w0.356: 78.82,50.49 78.64,50.67 75.56,50.67 75.18,51.05 75.18,54.48 75.44,54.74 R36.2
DPTX_GND: length 16.2
  TOP w0.356: J9.21 83.01,58.93 ; J9.21 83.01,57.57 ; J9.21 84.49,58.25 ; J9.21 81.53,58.25 ; J9.23 89.77,58.93 ; J9.23 88.54,58.25 ; J9.23 89.77,57.57 ; J9.23 91,58.25 ; 81.53,41.74 J9.22 ; J9.22 83.01,42.42 ; J9.22 84.49,41.74 ; J9.22 83.01,41.06 ; 88.54,41.74 J9.24 ; J9.24 91,41.74 ; J9.24 89.77,42.42 ; J9.24 89.77,41.06
DSI_A0N: length 42.4
  TOP w0.076: 36.17,44.27 36.17,44.75 36.3,44.88 U1.J3
  TOP w0.127: 36.17,44.27 36.17,43.89 35.27,42.99 35.27,42.16 33.69,40.58 30.07,40.58 29.66,40.99 29.66,41.96 29.1,42.53 28.3,42.53 27.73,41.96 27.73,40.99 27.32,40.58 26.77,40.58 23.49,43.86 23.49,44.44 24.13,45.08 24.13,45.88 23.57,46.45 22.77,46.45 22.12,45.8 21.54,45.8 21.13,46.21 21.13,46.79 21.62,47.28 21.78,47.43 21.78,48.31 21.29,48.8 20.41,48.8 20.26,48.64 19.77,48.15 19.19,48.15 17.51,49.84 17.51,49.94 17.58,50.02 17.58,50.12 17.51,50.2 17.4,50.2 17.33,50.12 17.22,50.12 17.15,50.2 17.15,50.3 17.22,50.38 17.22,50.48 17.15,50.56 17.04,50.56 16.97,50.48 16.86,50.48 16.79,50.56 16.79,50.66 16.87,50.74 16.87,50.84 16.79,50.92 16.69,50.92 16.61,50.84 16.5,50.84 16.43,50.91 16.43,51.02 16.51,51.1 16.51,51.2 16.43,51.28 16.33,51.28 16.25,51.2 16.15,51.2 16.07,51.27 16.07,51.38 16.15,51.45 16.15,51.56 16.07,51.63 15.97,51.63 15.89,51.56 15.79,51.56 15.6,51.75 12.26,51.75 12.14,51.87 J4.35
  vias: v1(12.18,51.87)
DSI_A0P: length 41.7
  TOP w0.076: 36.44,44.27 36.44,44.66 36.55,44.77 36.55,45.15 U1.H3
  TOP w0.127: J4.33 12.17,51.37 12.28,51.48 15.49,51.48 19.08,47.89 19.88,47.89 20.52,48.53 21.18,48.53 21.51,48.2 21.51,47.54 20.87,46.9 20.87,46.1 21.43,45.53 22.23,45.53 22.88,46.18 23.46,46.18 23.86,45.77 23.86,45.19 23.22,44.55 23.22,43.75 26.66,40.31 27.43,40.31 28,40.88 28,41.85 28.41,42.26 28.99,42.26 29.4,41.85 29.4,40.88 29.96,40.31 33.8,40.31 35.53,42.05 35.53,42.88 36.44,43.78 36.44,44.27
  vias: v1(12.18,51.37)
DSI_A1N: length 42.4
  TOP w0.076: U1.J4 36.8,44.38
  TOP w0.127: J4.27 12.15,48.87 12.27,48.75 13.58,48.75 13.76,48.57 13.87,48.57 13.9,48.59 14,48.59 14.08,48.52 14.08,48.41 14.05,48.39 14.05,48.28 14.12,48.21 14.23,48.21 14.26,48.23 14.36,48.23 14.43,48.16 14.43,48.06 14.41,48.03 14.41,47.92 14.48,47.85 14.59,47.85 14.61,47.88 14.72,47.88 14.79,47.8 14.79,47.7 14.77,47.67 14.77,47.56 14.84,47.49 14.95,47.49 14.97,47.52 15.08,47.52 15.15,47.44 15.15,47.34 15.13,47.31 15.13,47.2 15.2,47.13 15.31,47.13 15.33,47.16 15.44,47.16 15.51,47.08 15.51,46.98 15.49,46.95 15.49,46.85 15.56,46.77 15.67,46.77 15.69,46.8 15.8,46.8 15.87,46.72 15.87,46.62 15.85,46.59 15.85,46.49 15.92,46.41 16.02,46.41 16.05,46.44 16.16,46.44 16.23,46.36 16.23,46.26 16.2,46.23 16.2,46.13 16.28,46.05 16.38,46.05 16.41,46.08 16.52,46.08 16.59,46 16.59,45.9 16.56,45.87 16.56,45.77 16.7,45.63 16.9,45.63 17.08,45.46 17.08,45.25 17.38,44.95 17.96,44.95 18.37,45.37 18.53,45.53 19.49,45.53 19.9,45.12 19.9,44.16 19.74,44 19.32,43.59 19.32,43.01 19.73,42.6 20.31,42.6 20.73,43.02 20.88,43.17 21.72,43.17 22.25,42.64 22.25,41.81 22.09,41.65 21.68,41.23 21.68,40.66 23.49,38.84 24.09,38.84 24.63,39.38 25.88,39.38 26.43,38.84 27.41,38.84 27.96,39.38 29.21,39.38 29.75,38.84 30.74,38.84 31.28,39.38 32.54,39.38 33.08,38.84 34.24,38.84 36,40.6 36,42.38 36.75,43.13 36.75,44.33 36.8,44.38
  vias: v1(12.19,48.87)
